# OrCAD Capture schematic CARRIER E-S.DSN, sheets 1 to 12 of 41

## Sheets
1 B0: size A4; title: Sistema Emulador Planta Generación Eólica; Carrier E/S para placa MicroZed; rev: 1.0; company: Oficina Técnica Universidad Carlos III de Madrid; note: OT-2017-4302
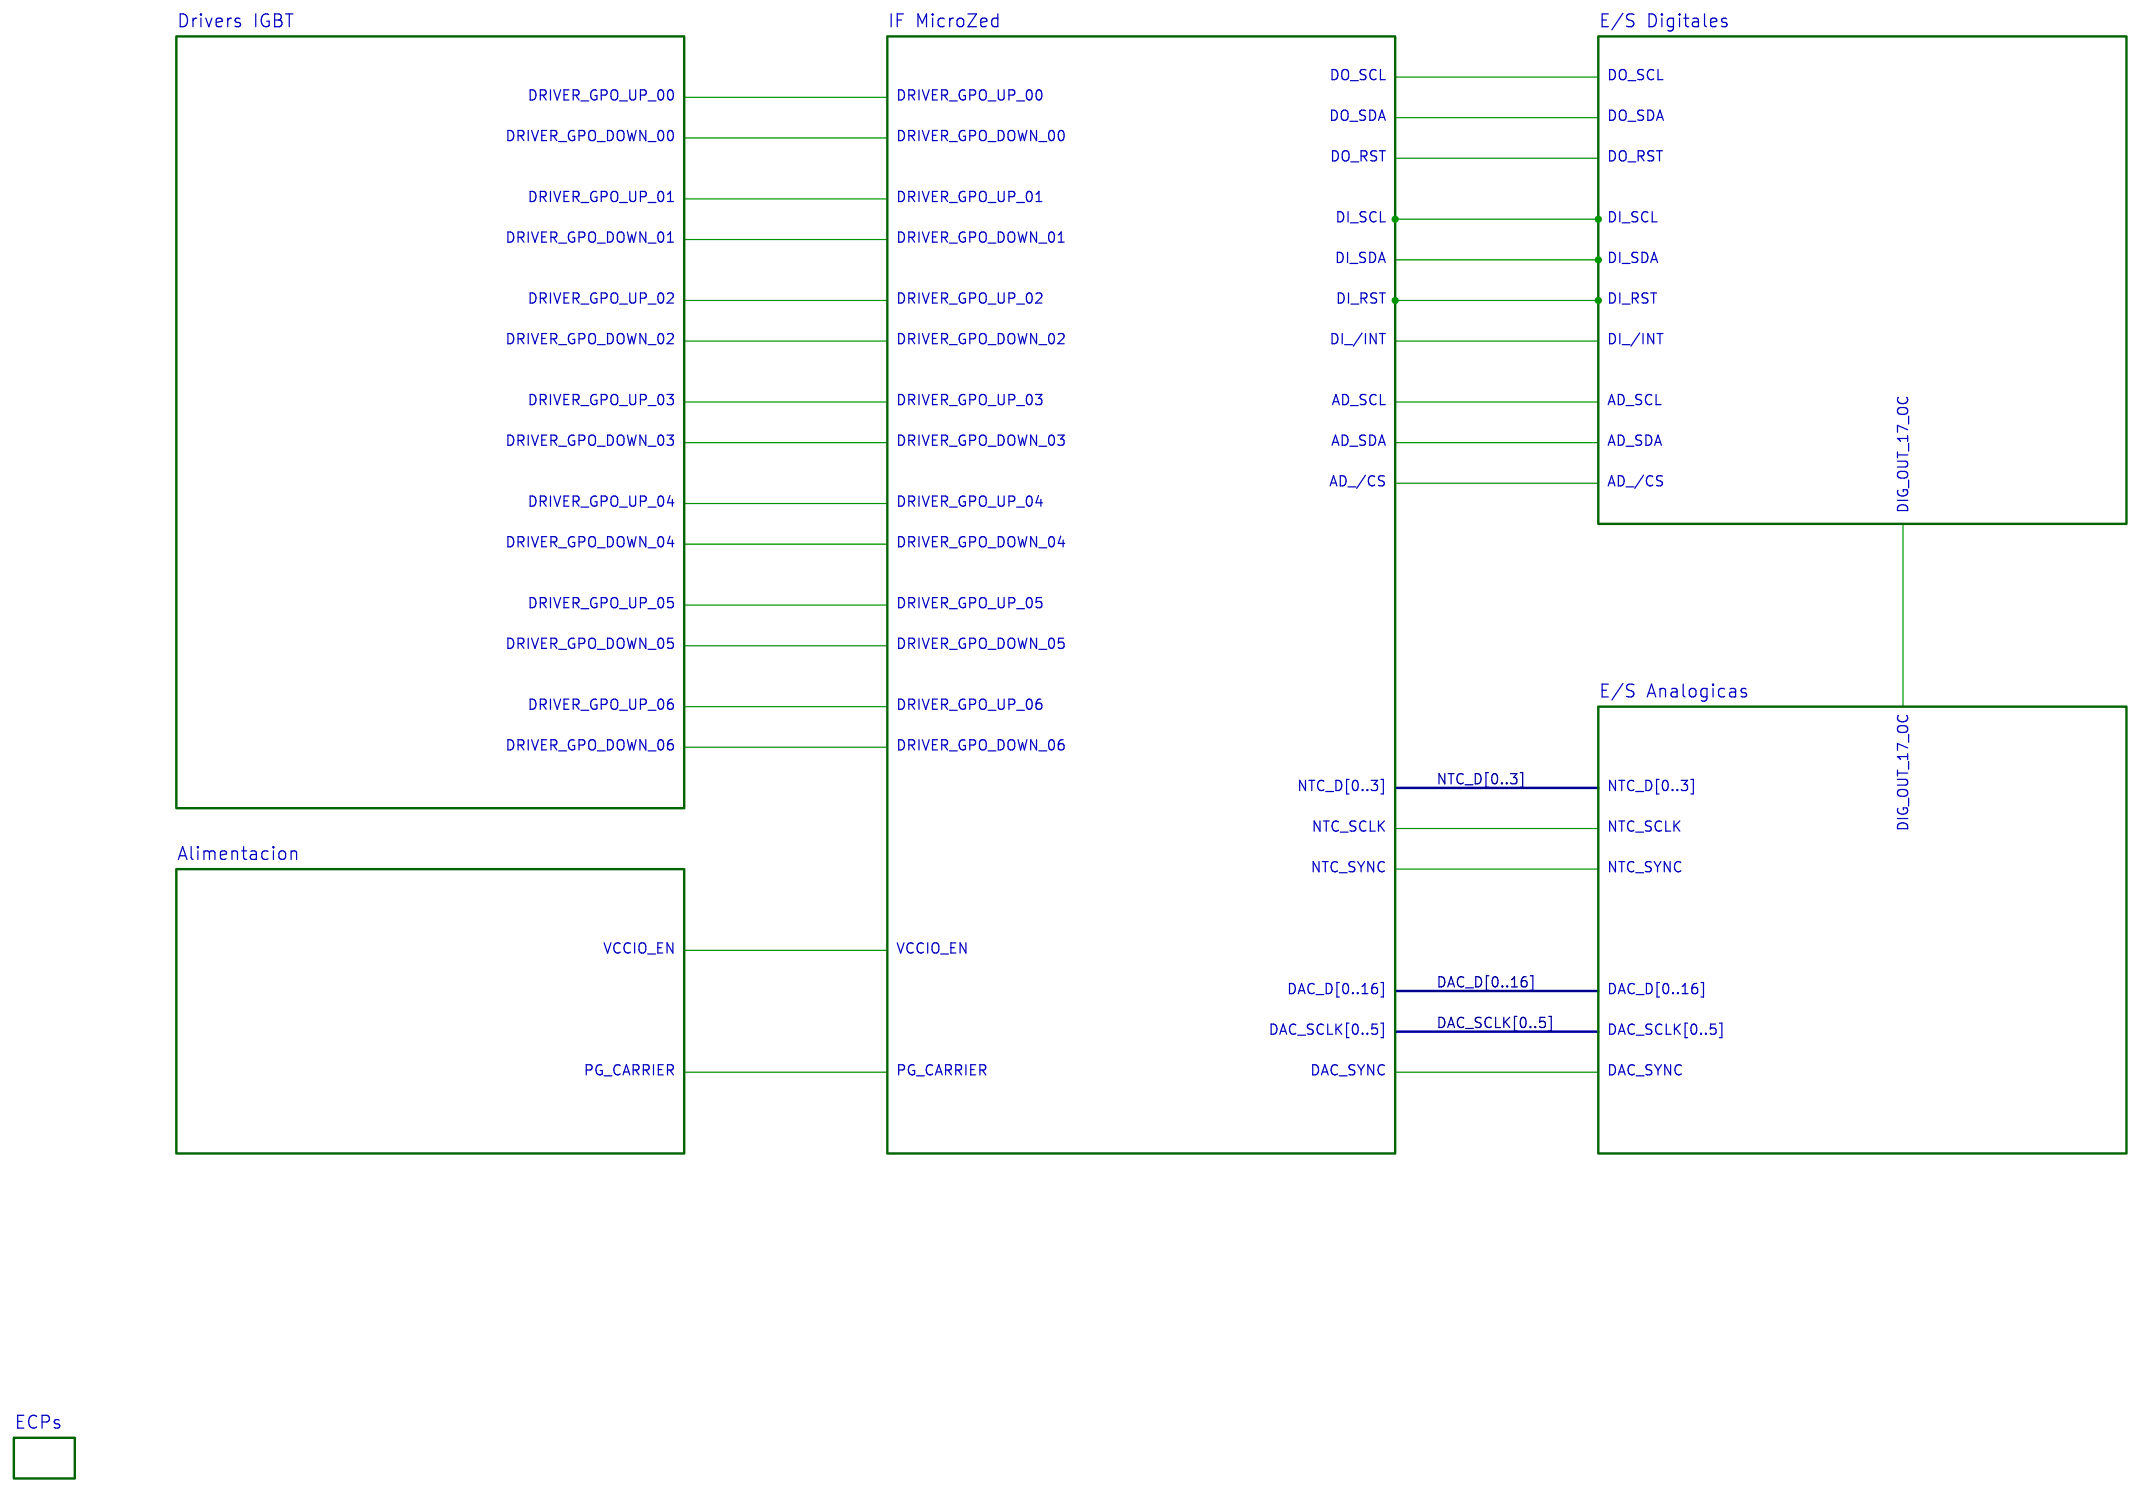
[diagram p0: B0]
2 B4B18
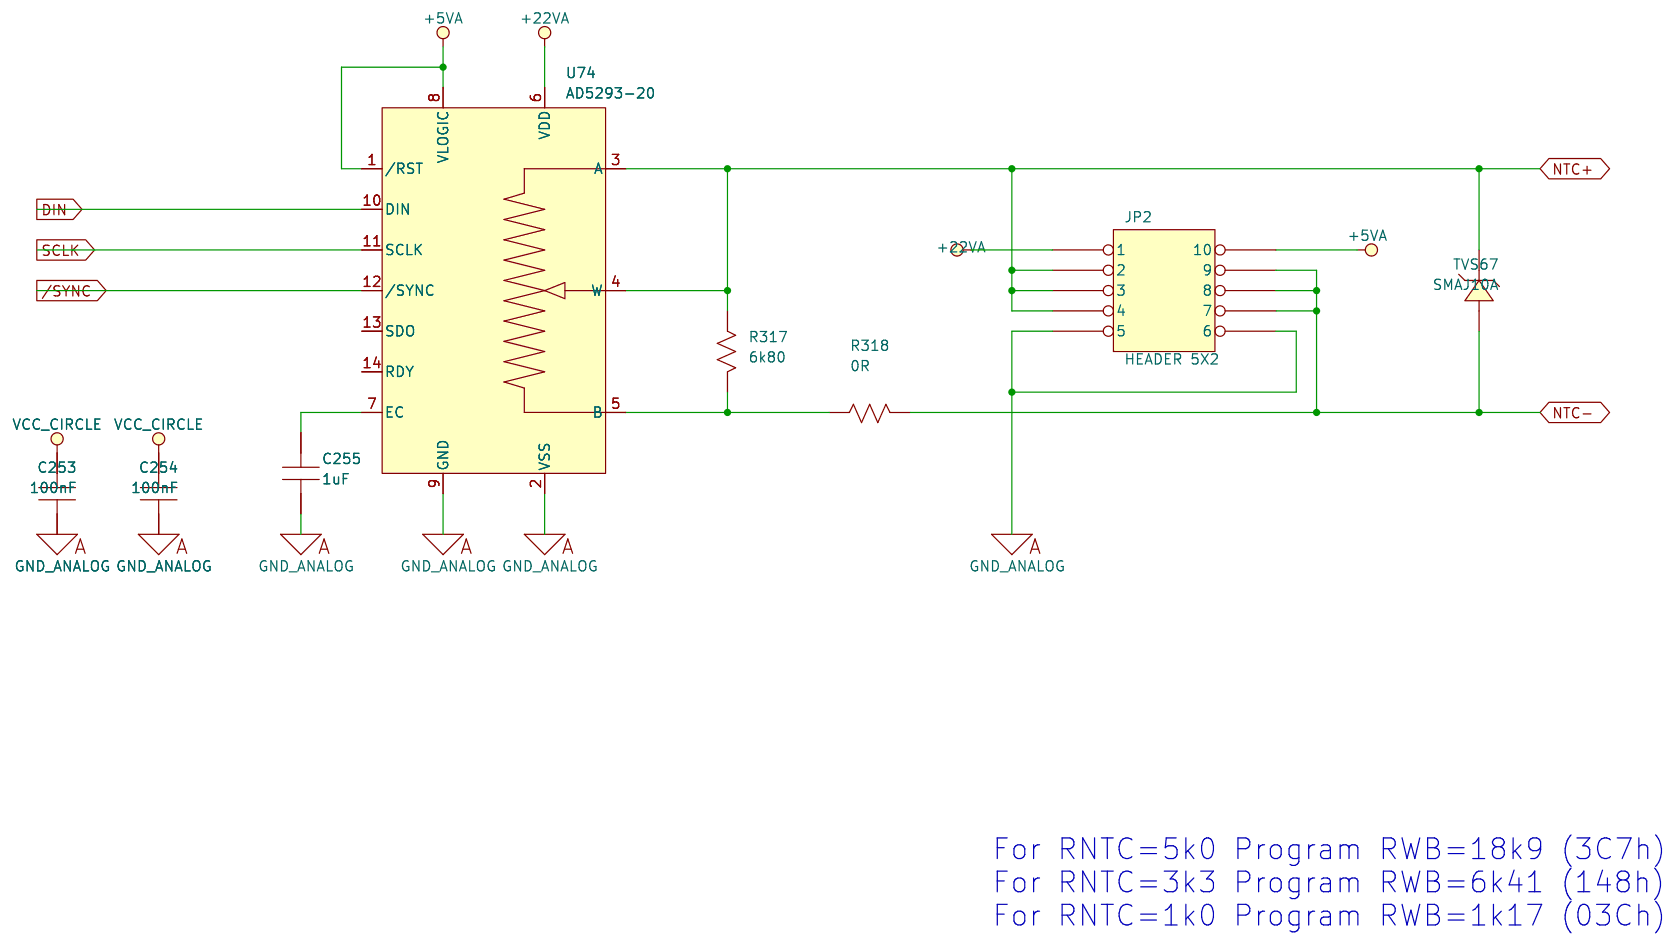
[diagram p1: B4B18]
3 B4B02
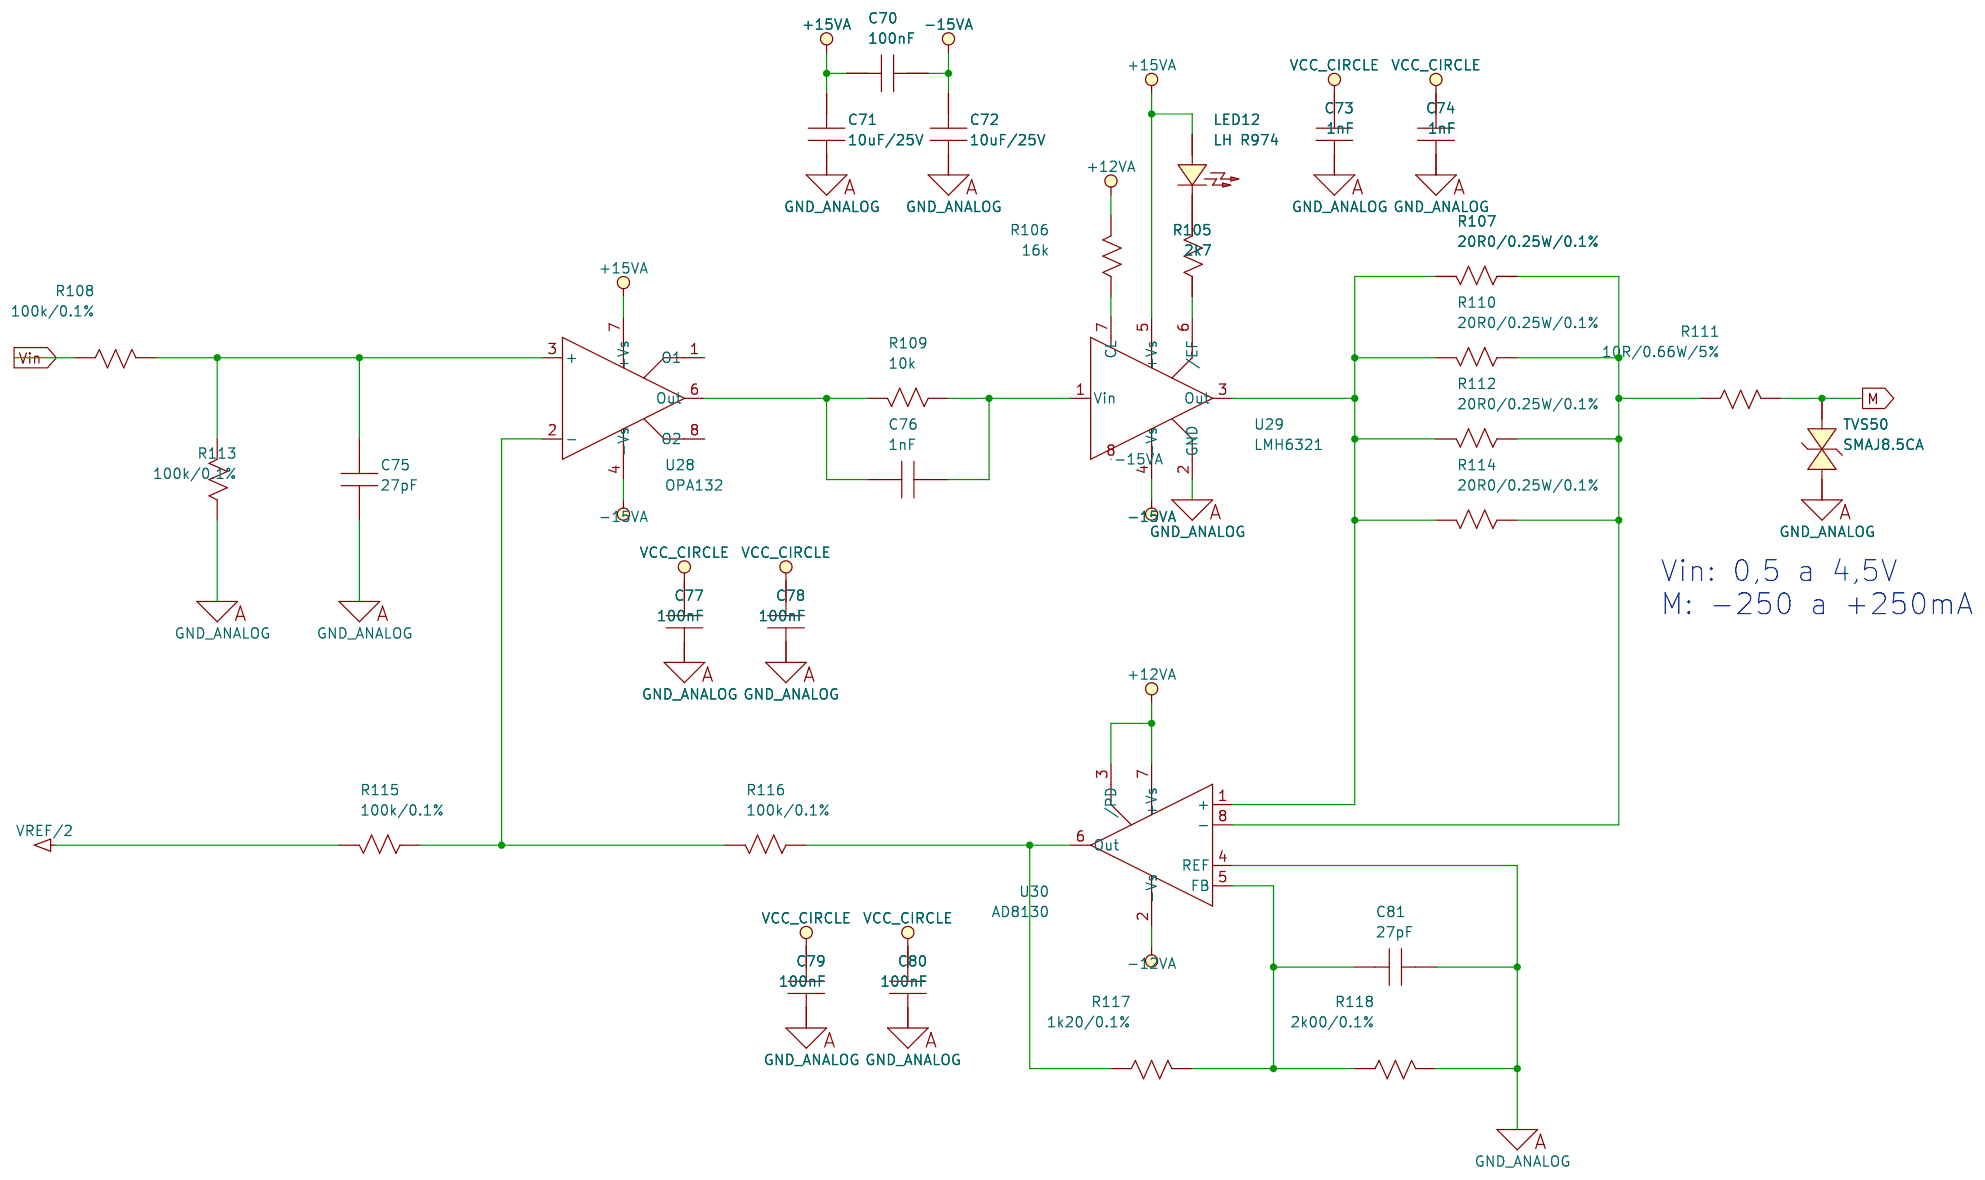
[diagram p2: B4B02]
4 B4B19
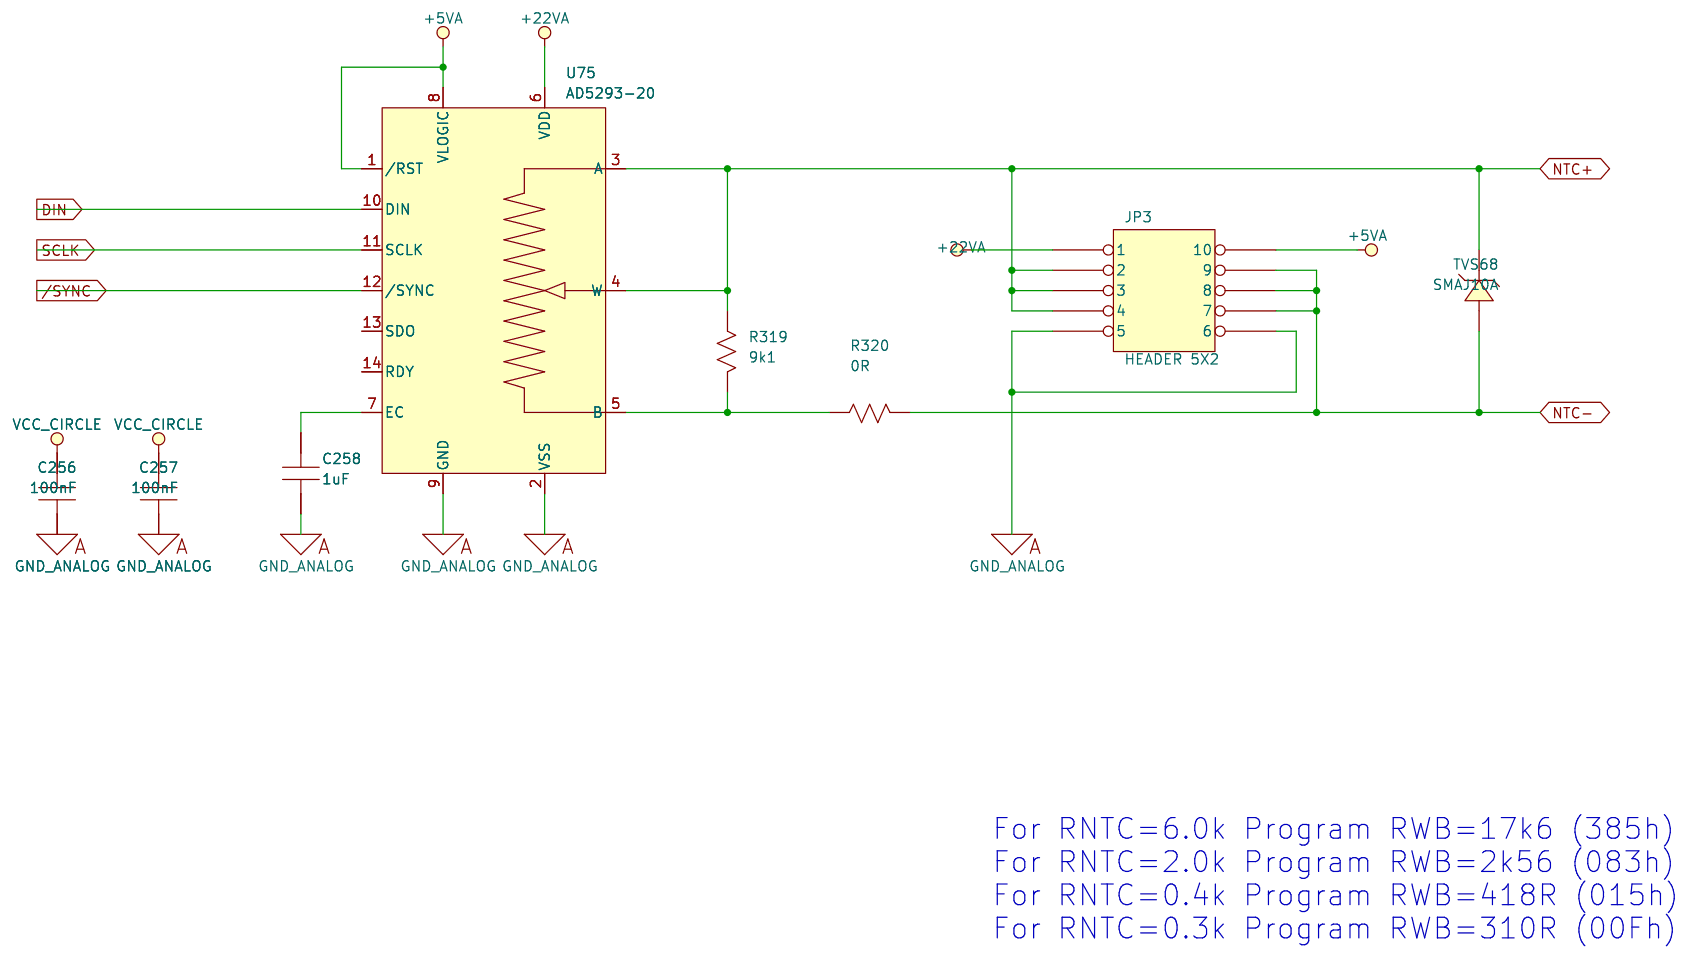
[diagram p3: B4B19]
5 B4B17
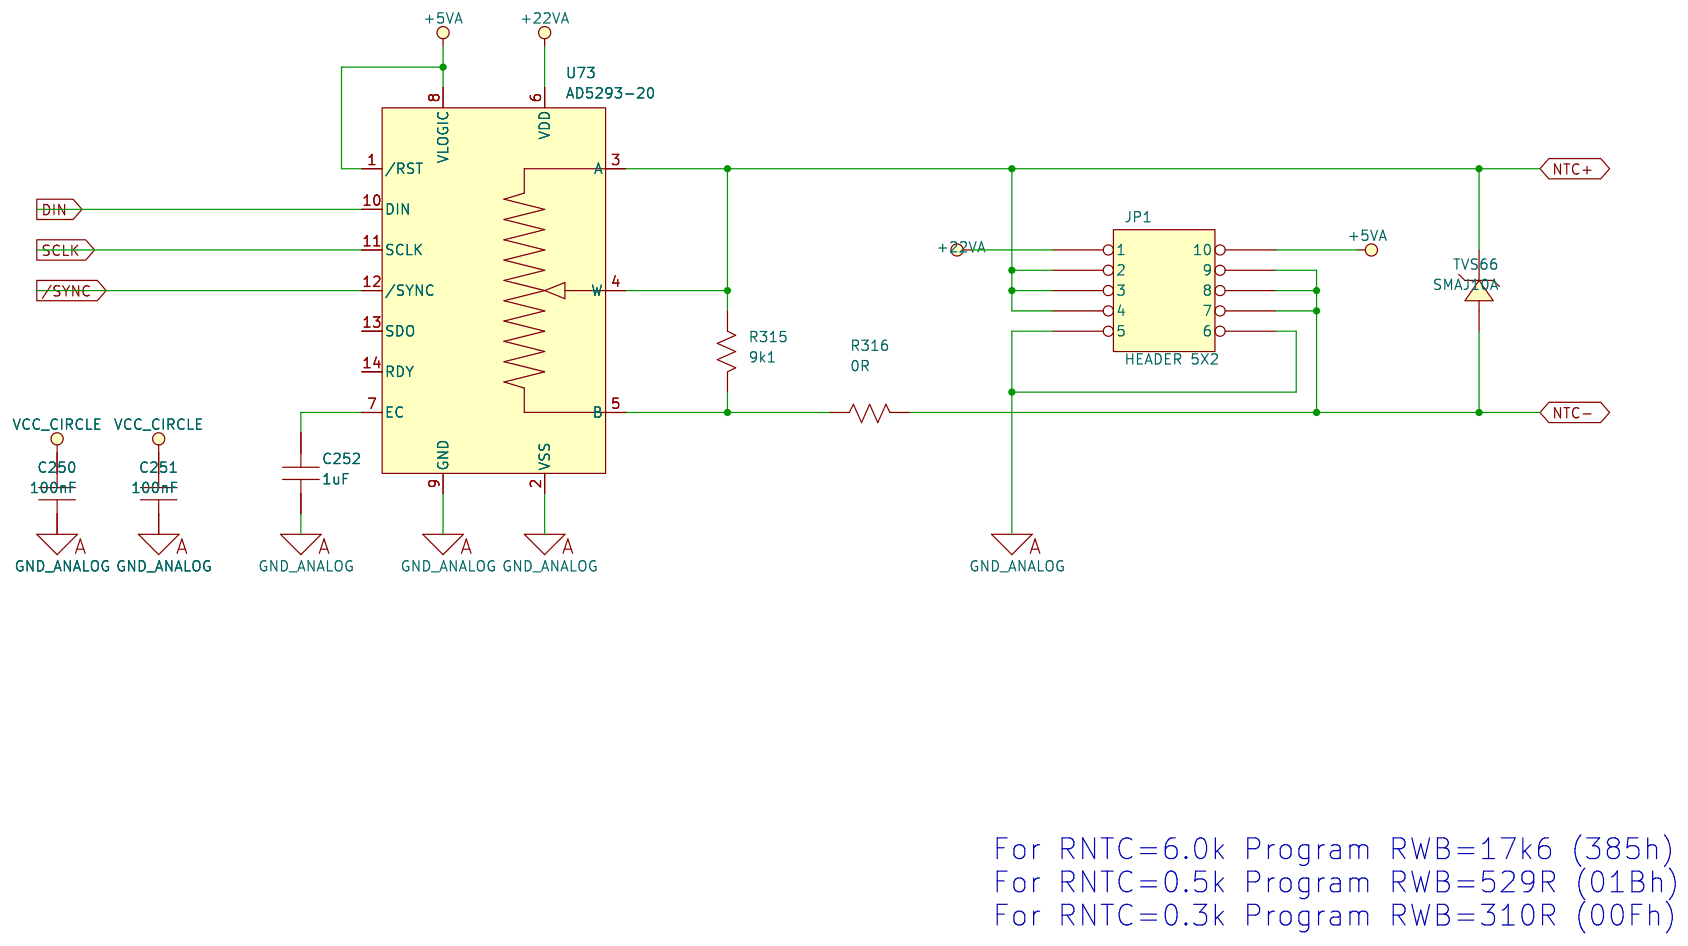
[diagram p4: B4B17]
6 B4B03
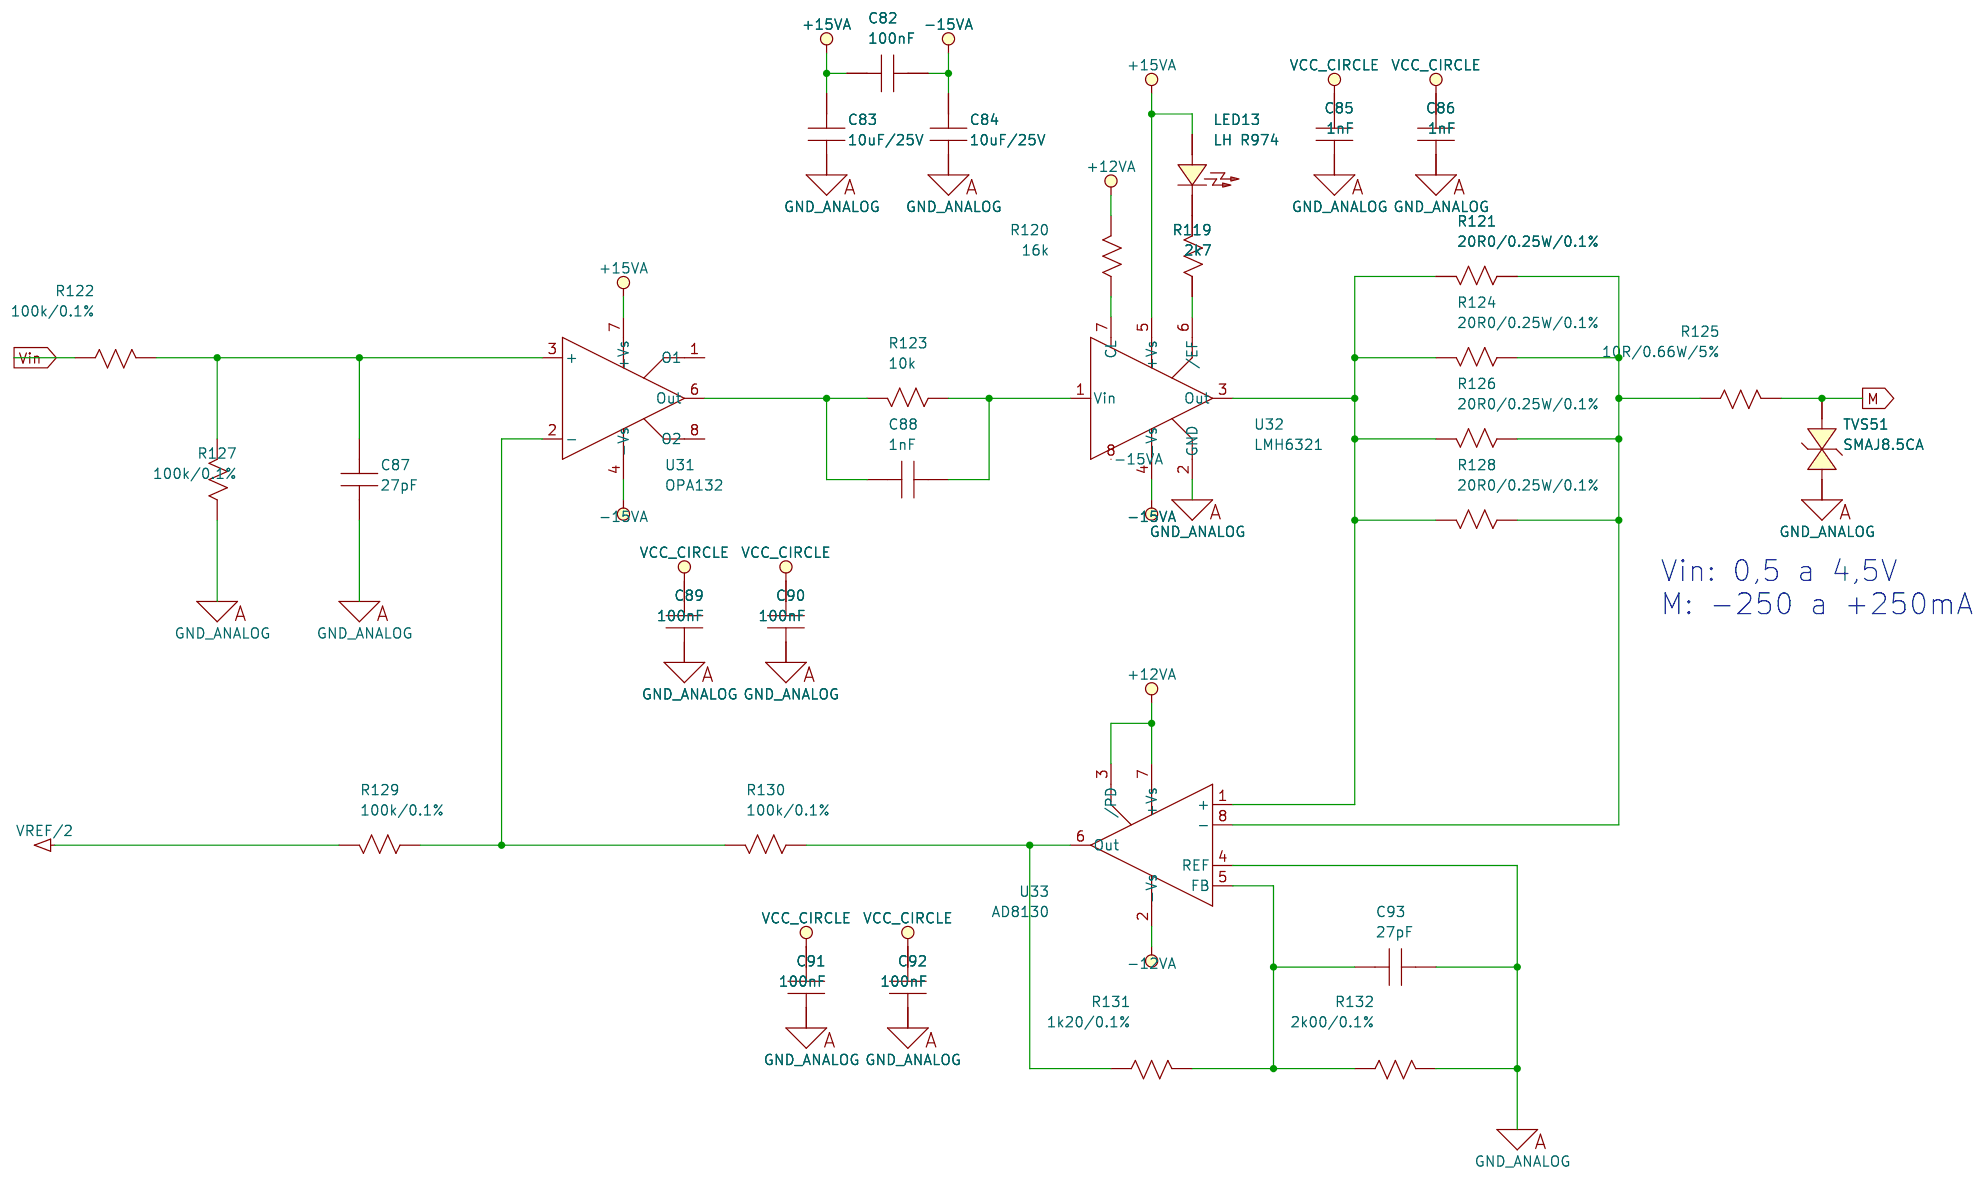
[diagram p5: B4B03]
7 B4B20
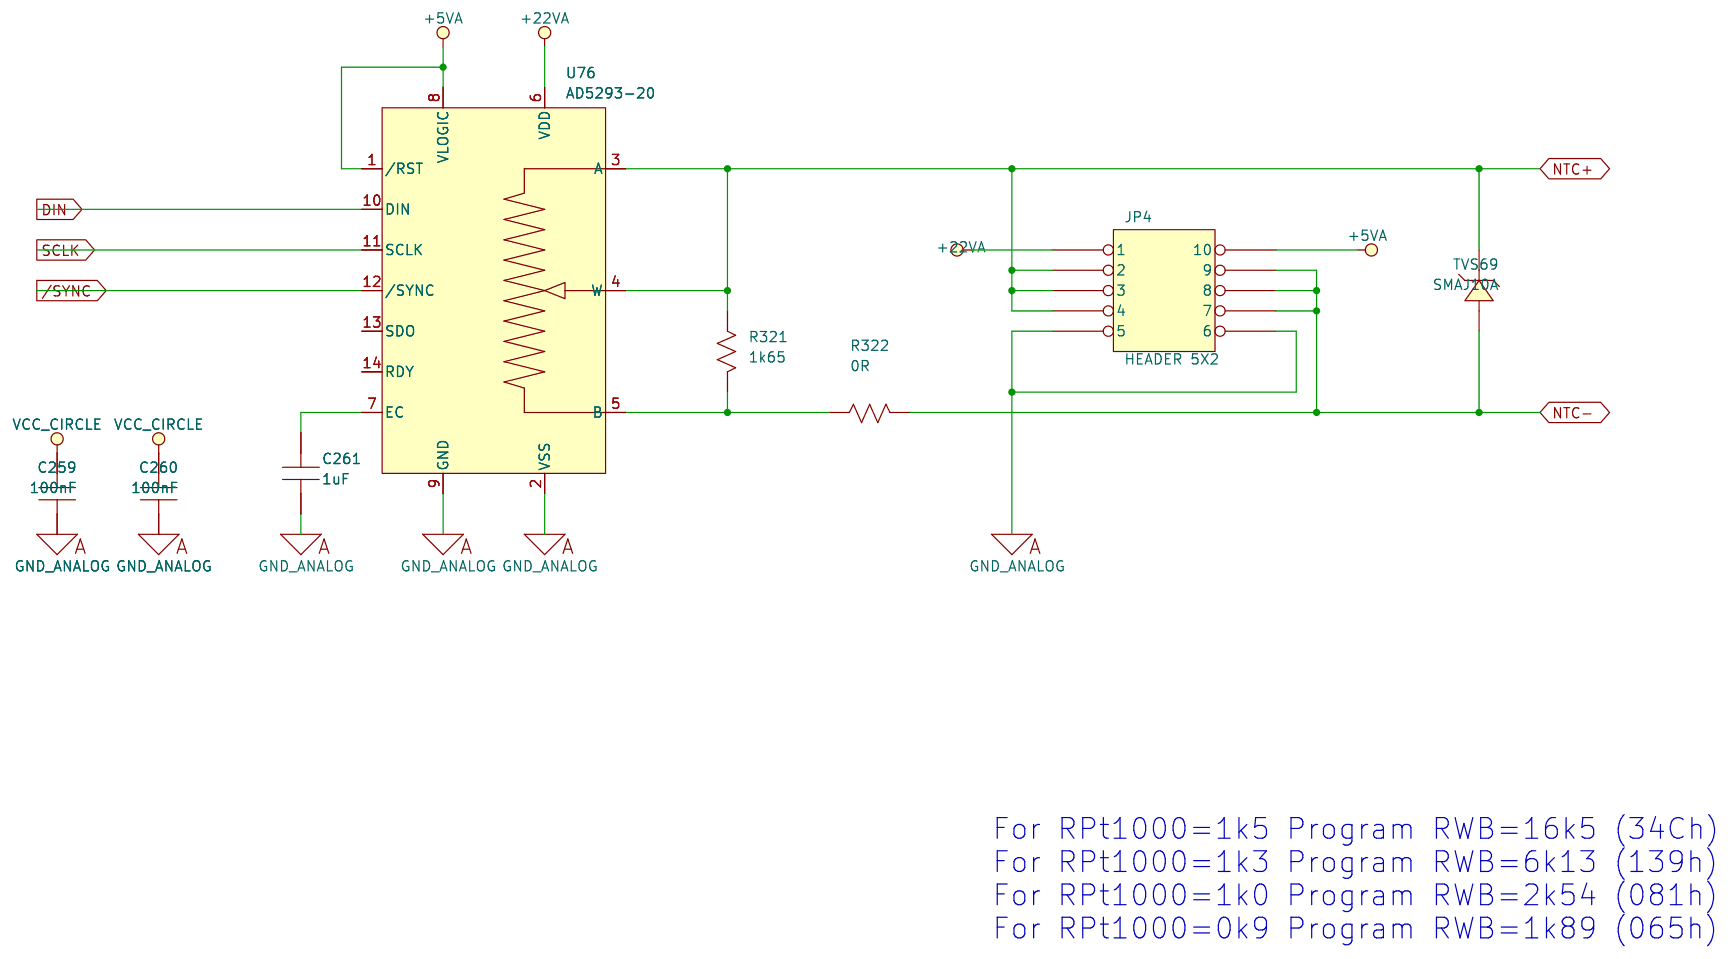
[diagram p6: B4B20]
8 B4B04
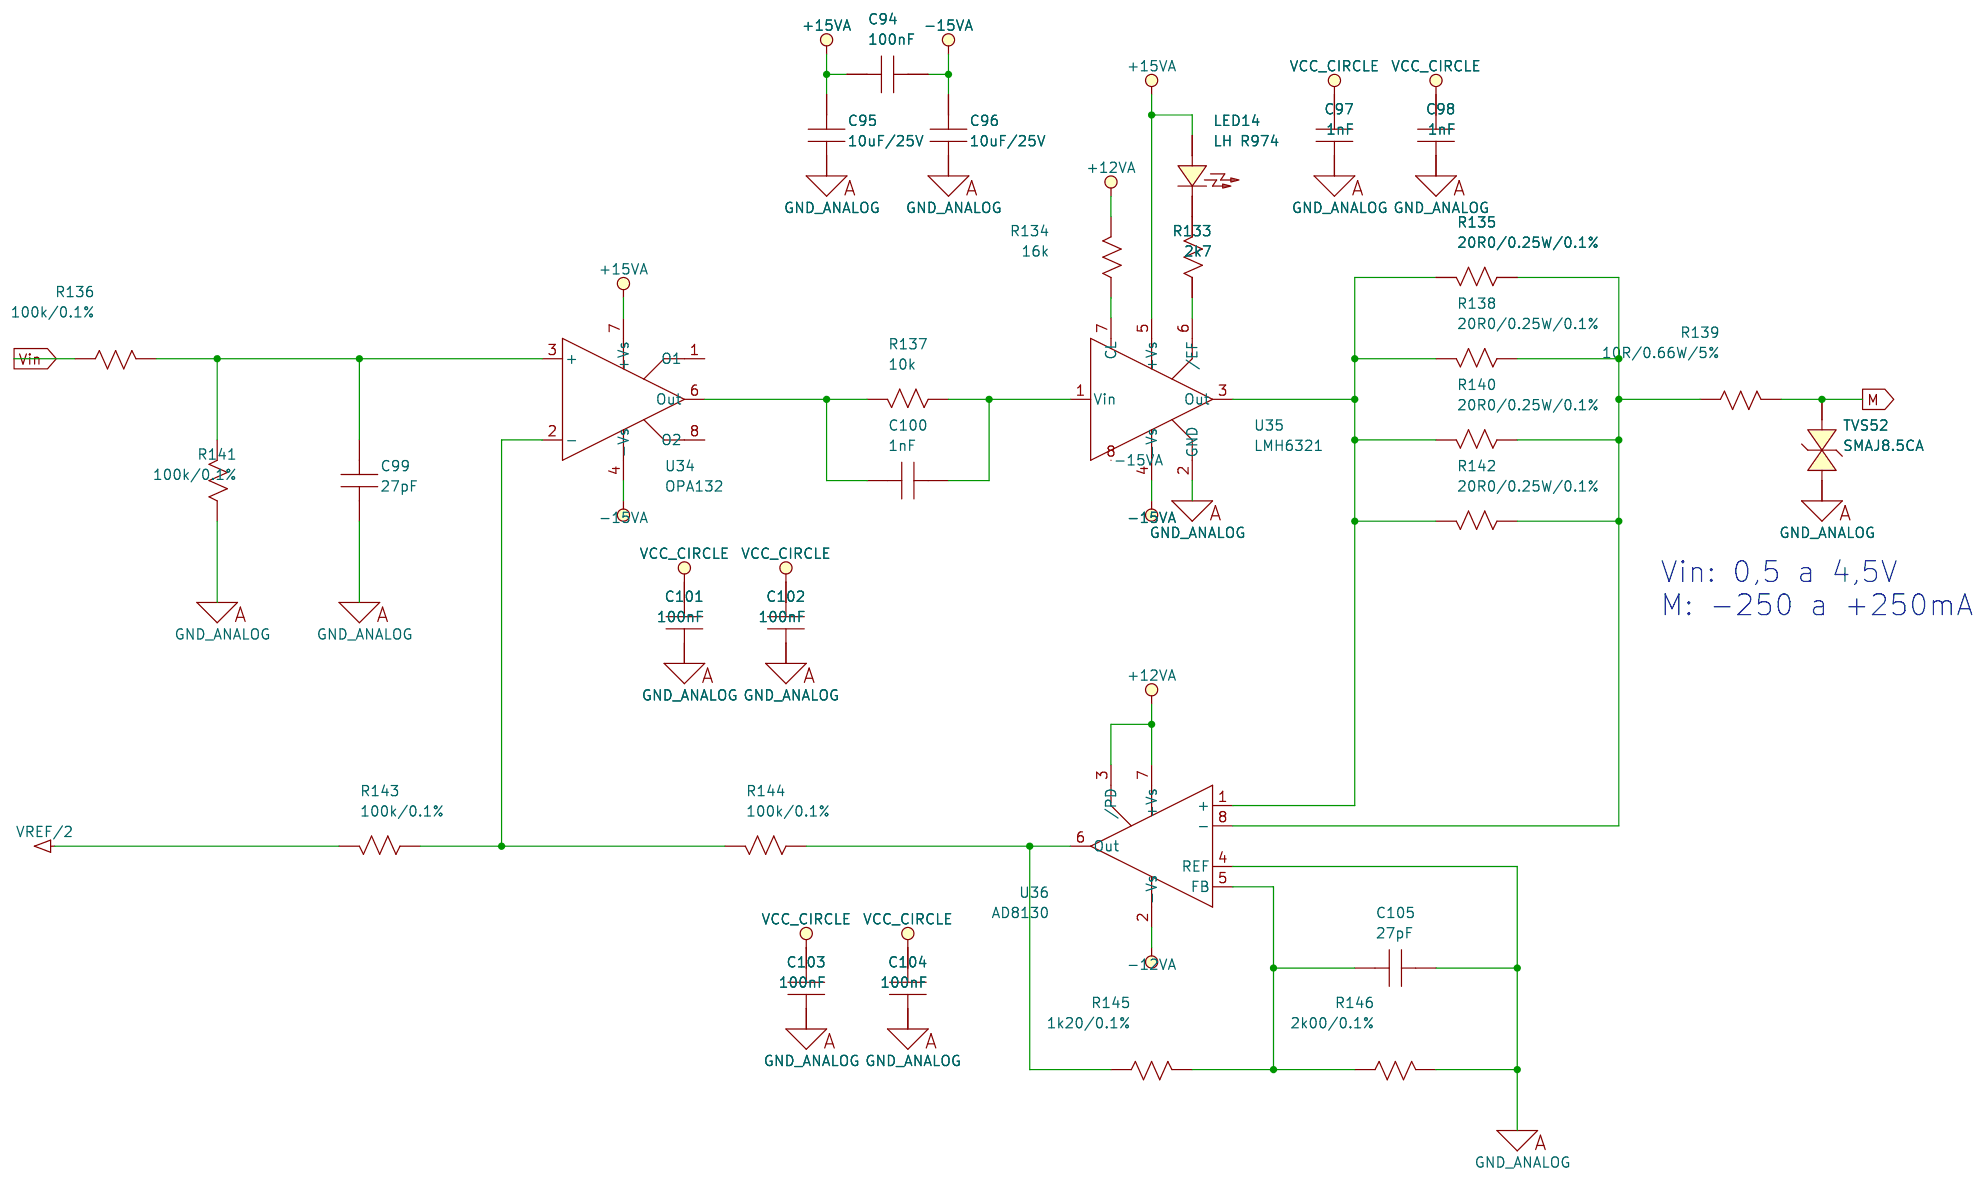
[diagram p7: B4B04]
9 B7B05
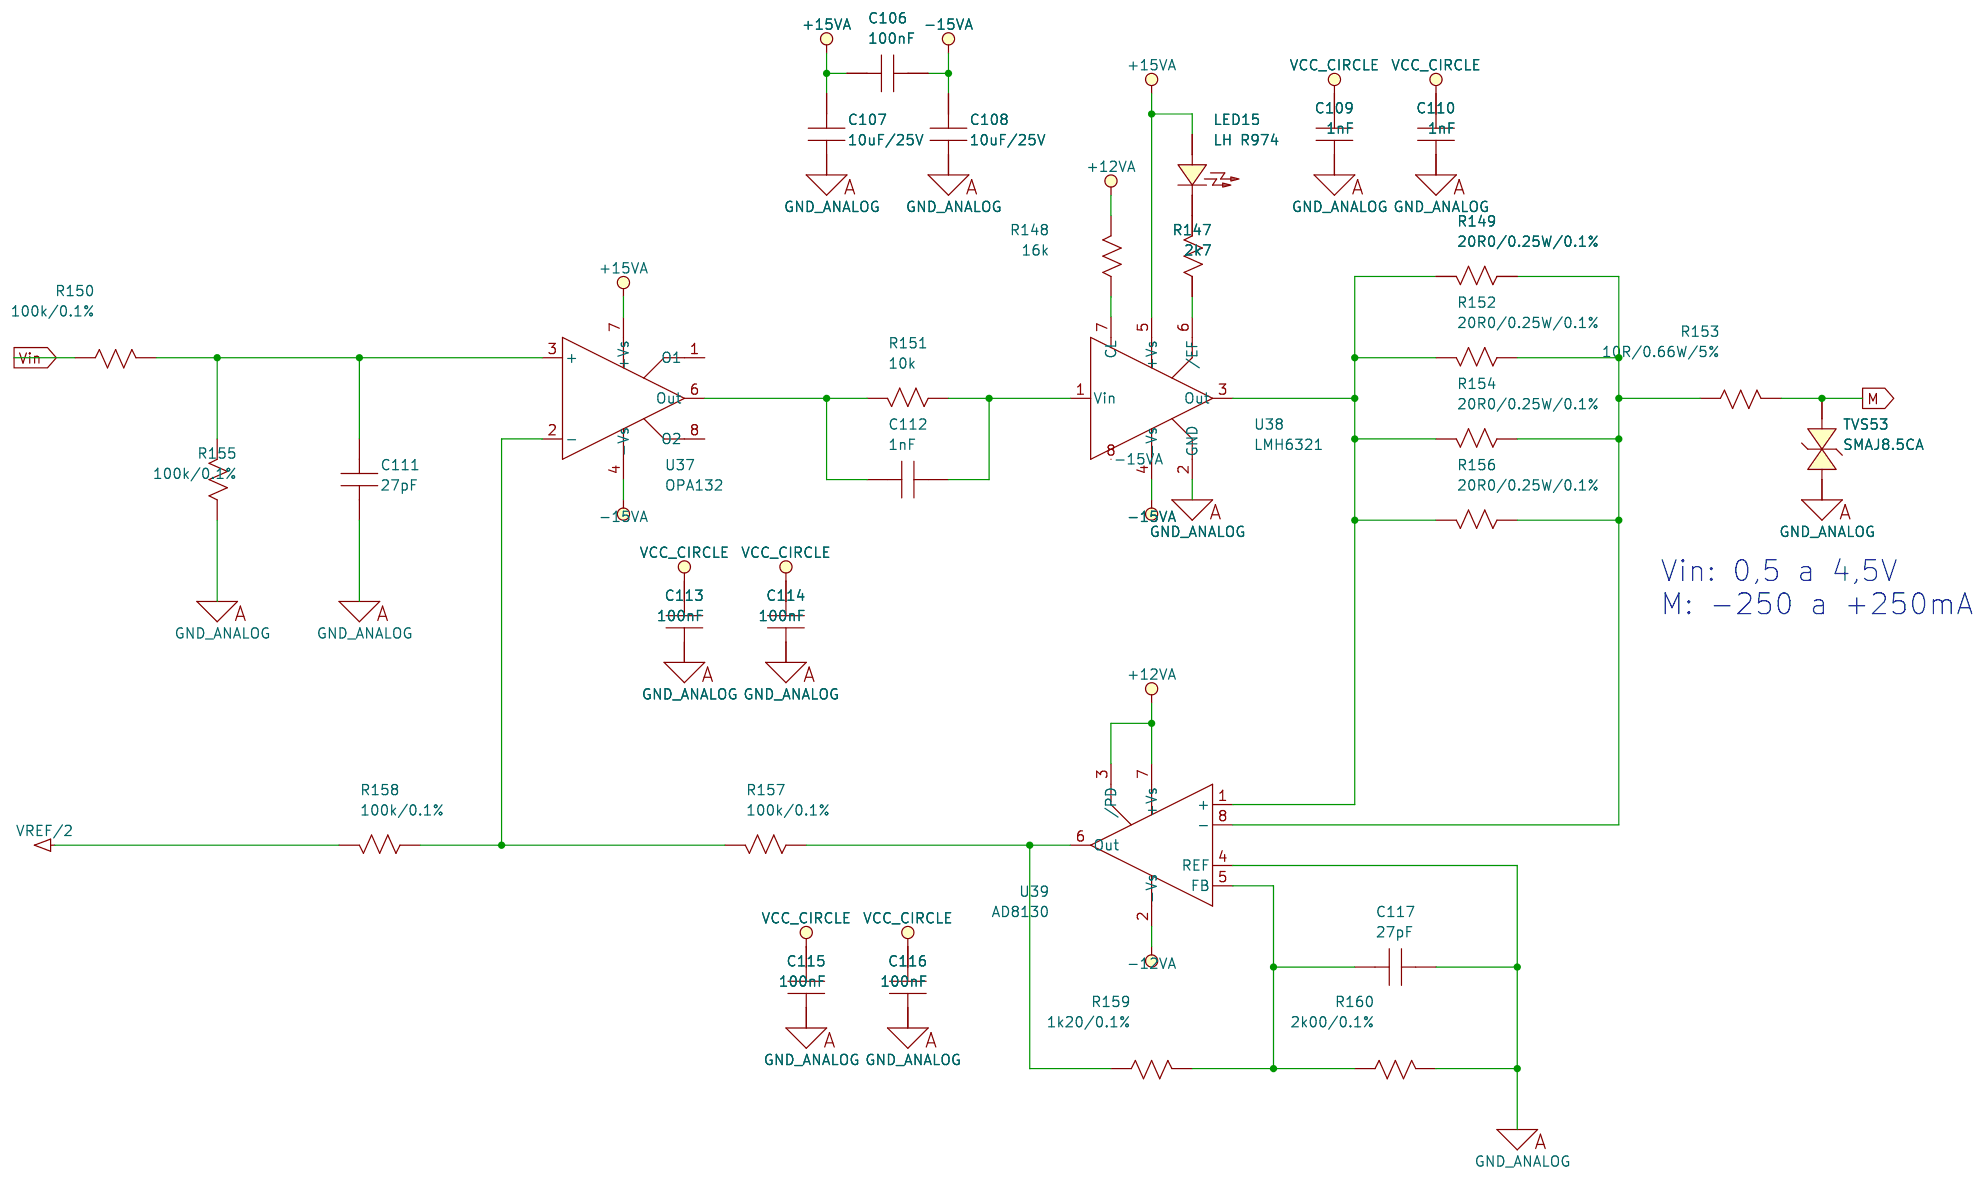
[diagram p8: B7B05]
10 B4B06
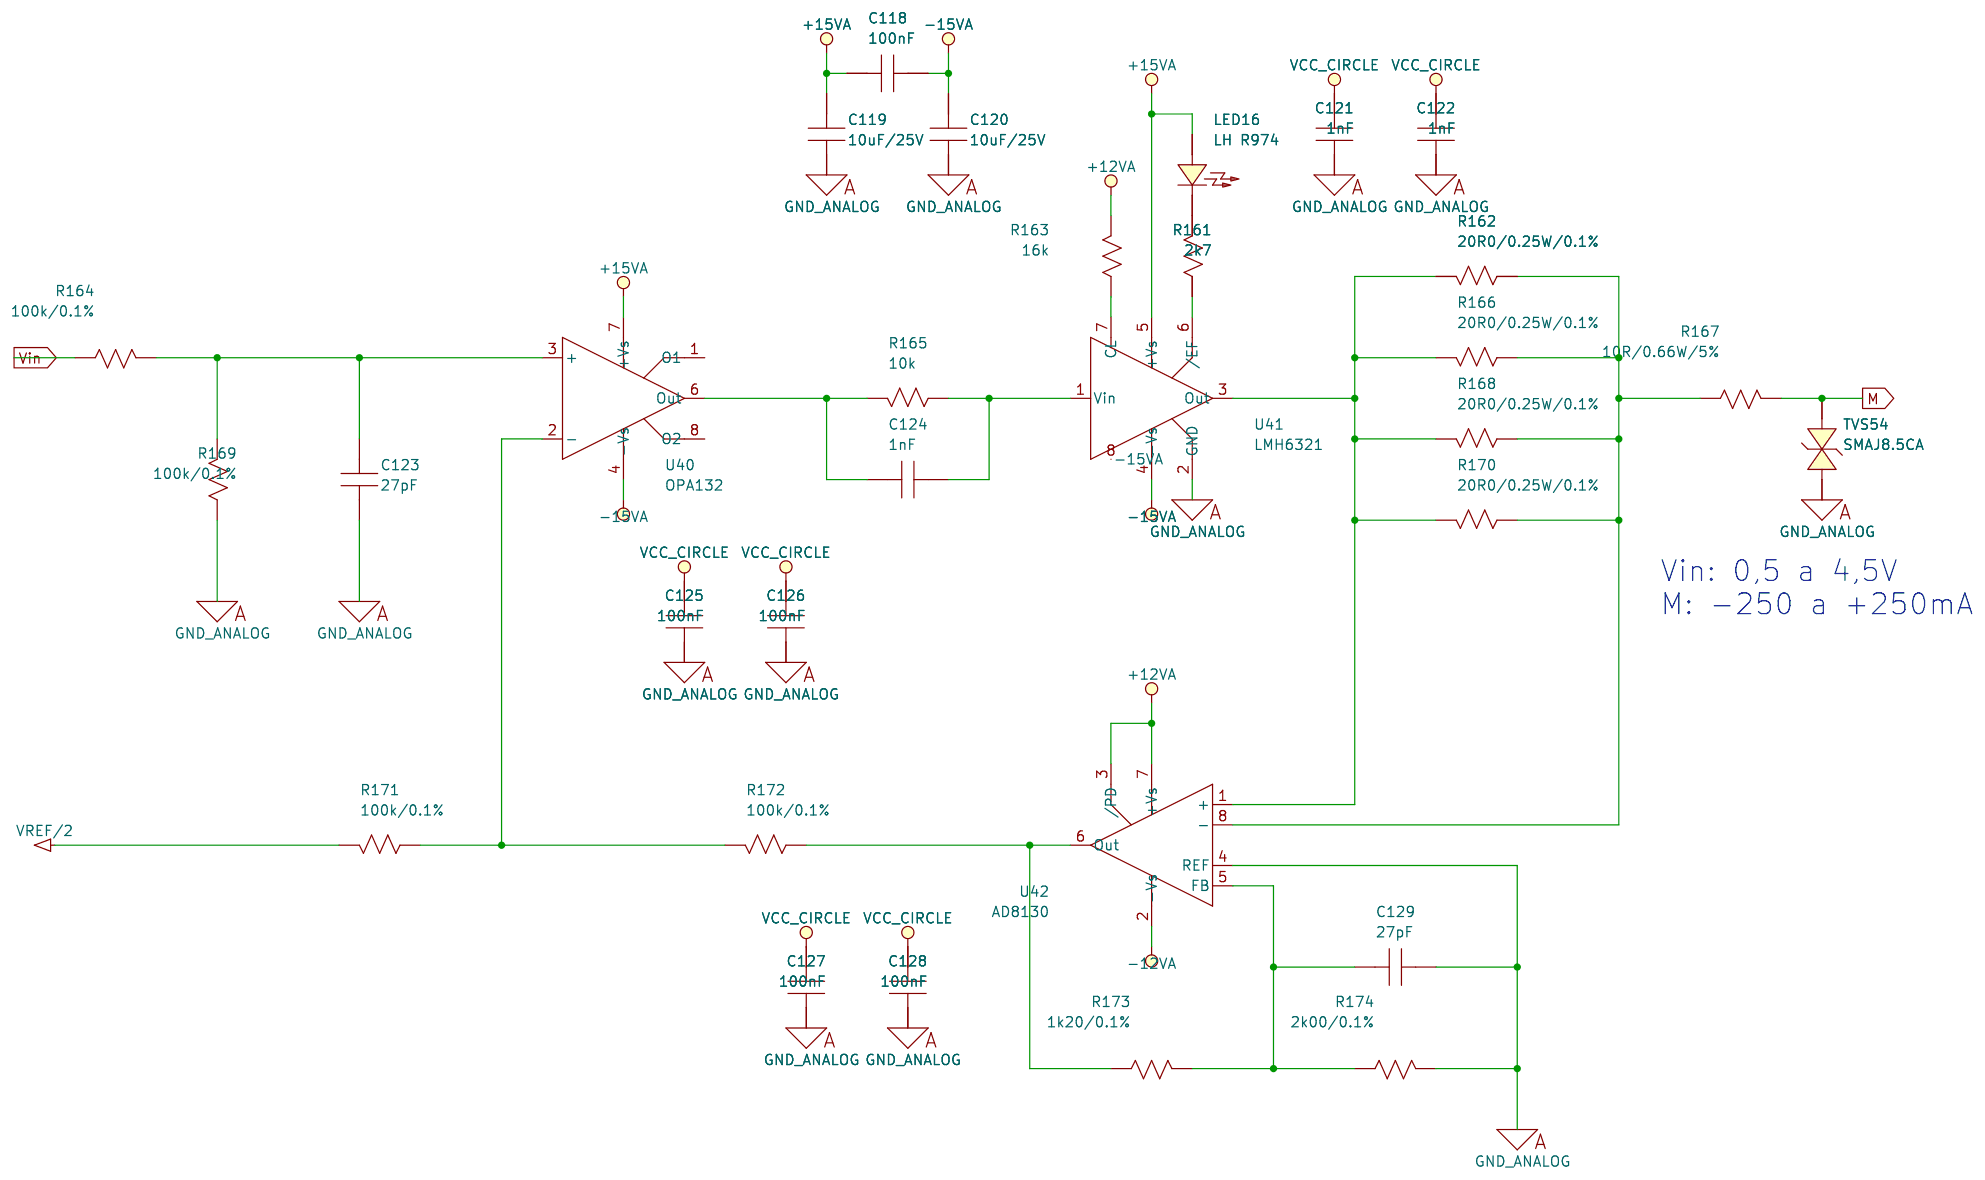
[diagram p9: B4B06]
11 B4B07
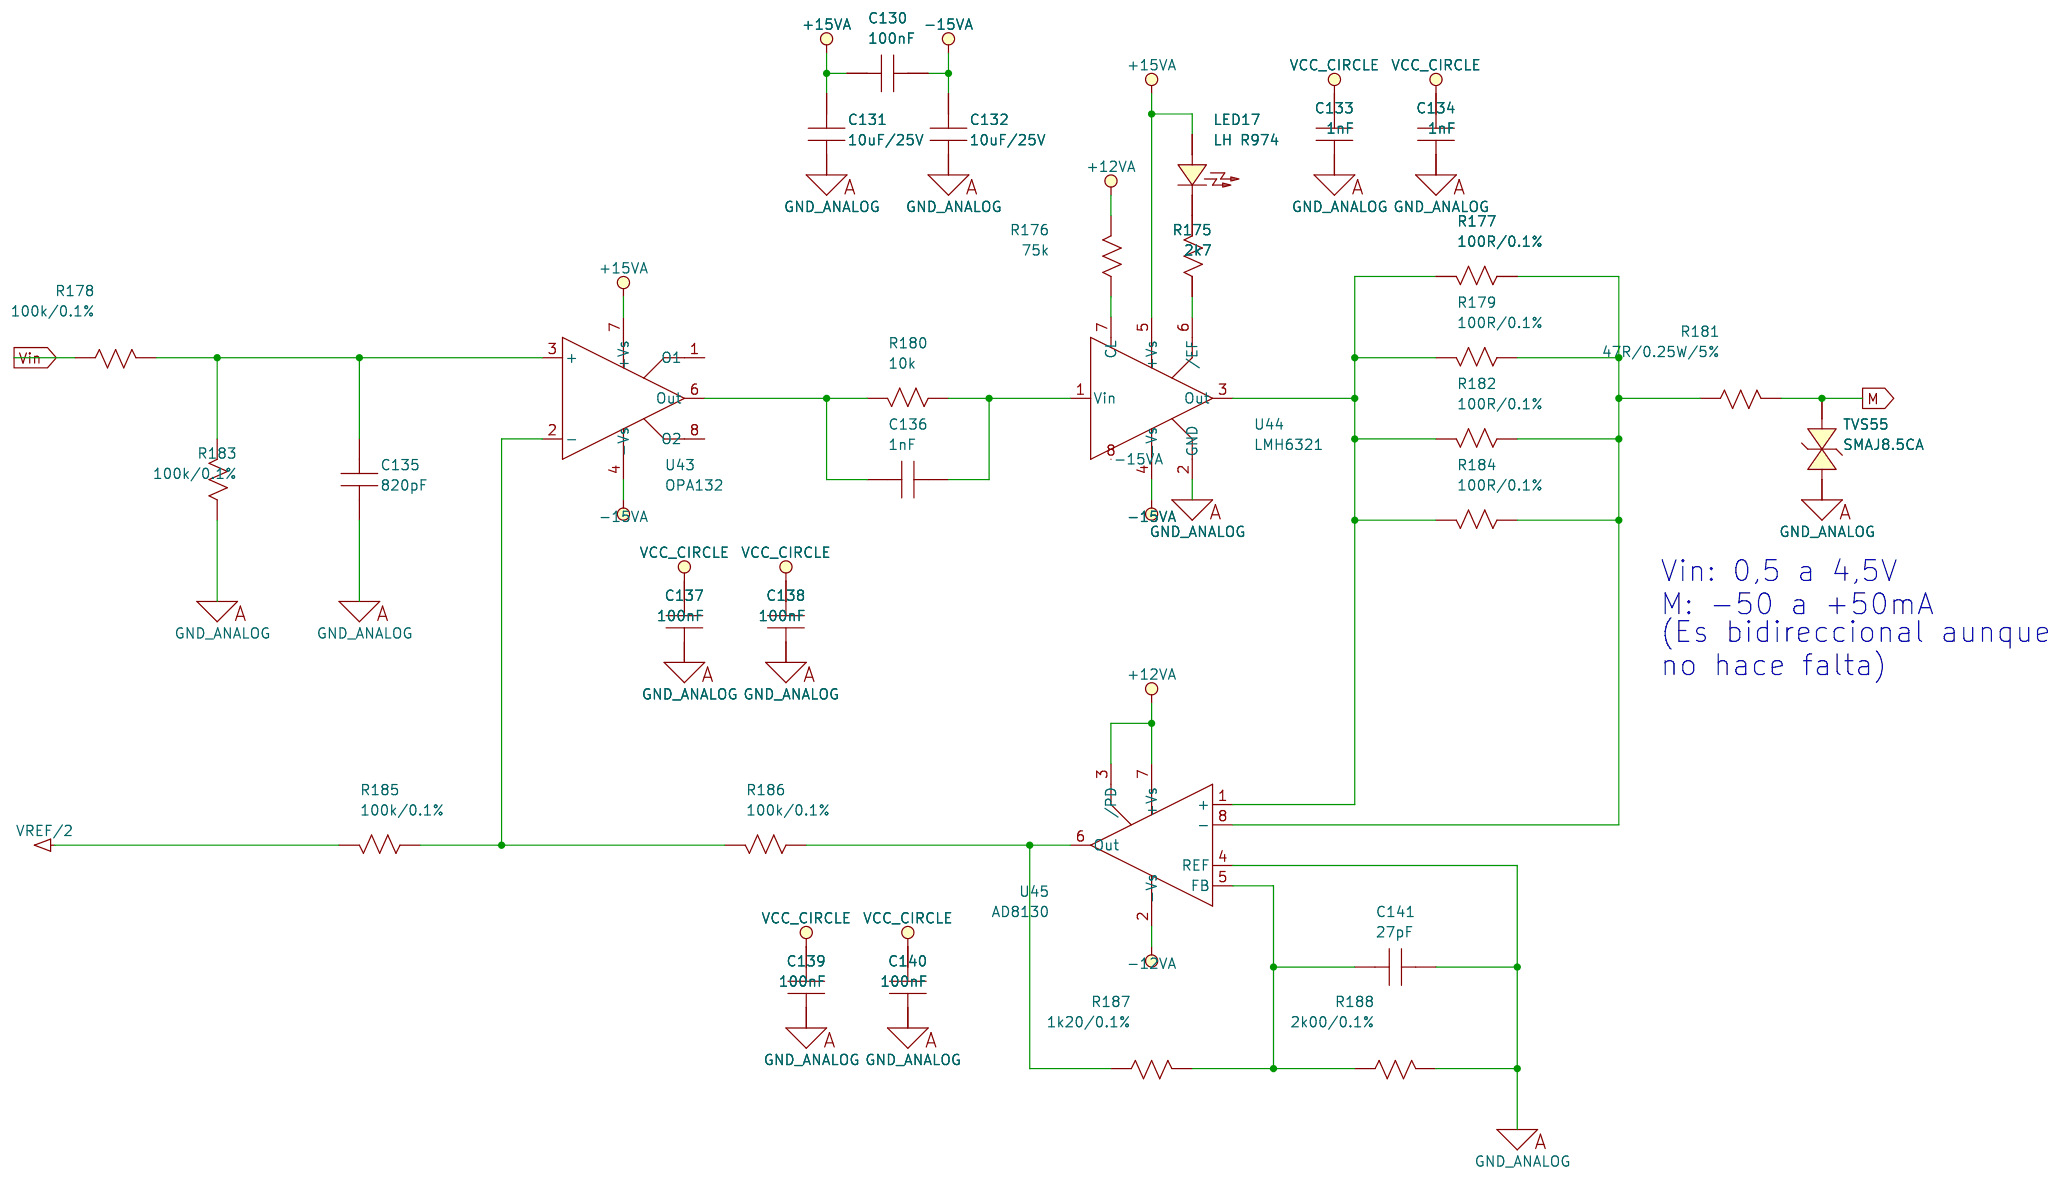
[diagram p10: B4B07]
12 B4B10
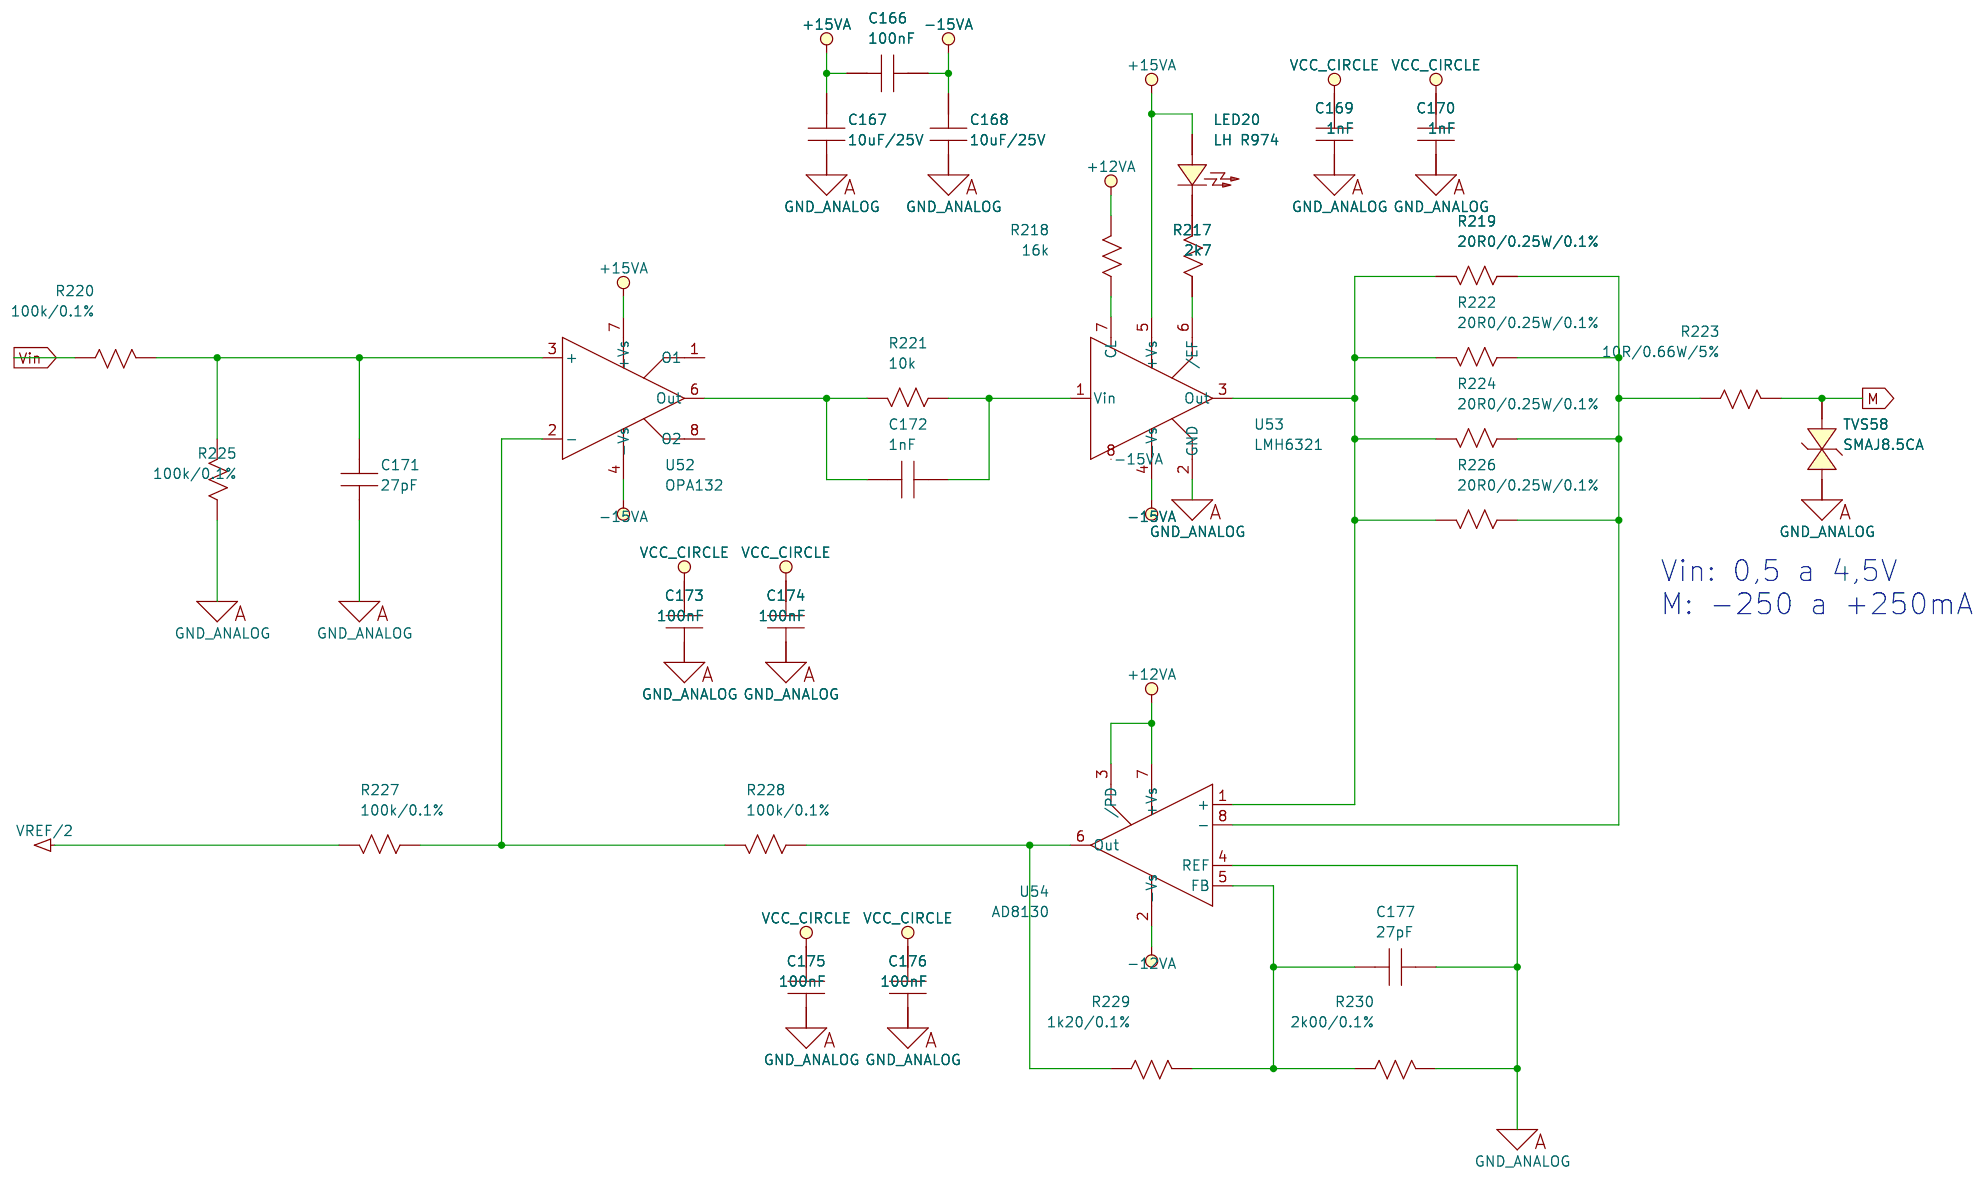
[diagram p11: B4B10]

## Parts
sheet B4B02
C70  100nF  [C/SM/0805/IPC-7351 (2005)/NORMAL]
C71  10uF/25V  [C/SM/1210/IPC-7351 (2005)/NORMAL]
C72  10uF/25V  [C/SM/1210/IPC-7351 (2005)/NORMAL]
C73  1nF  [C/SM/0805/IPC-7351 (2005)/NORMAL]
C74  1nF  [C/SM/0805/IPC-7351 (2005)/NORMAL]
C75  27pF  [C/SM/0805/IPC-7351 (2005)/NORMAL]
C76  1nF  [C/SM/0805/IPC-7351 (2005)/NORMAL]
C77  100nF  [C/SM/0805/IPC-7351 (2005)/NORMAL]
C78  100nF  [C/SM/0805/IPC-7351 (2005)/NORMAL]
C79  100nF  [C/SM/0805/IPC-7351 (2005)/NORMAL]
C80  100nF  [C/SM/0805/IPC-7351 (2005)/NORMAL]
C81  27pF  [C/SM/0805/IPC-7351 (2005)/NORMAL]
LED12  LH R974  [LED/SM/0805/IPC-7351 (2005)/NORMAL]
R105  2k7  [R/SM/0805/IPC-7351 (2005)/NORMAL]
R106  16k  [R/SM/0805/IPC-7351 (2005)/NORMAL]
R107  20R0/0.25W/0.1%  [R/SM/1206/IPC-7351 (2005)/NORMAL]
R108  100k/0.1%  [R/SM/0805/IPC-7351 (2005)/NORMAL]
R109  10k  [R/SM/0805/IPC-7351 (2005)/NORMAL]
R110  20R0/0.25W/0.1%  [R/SM/1206/IPC-7351 (2005)/NORMAL]
R111  10R/0.66W/5%  [R/SM/1206/IPC-7351 (2005)/NORMAL]
R112  20R0/0.25W/0.1%  [R/SM/1206/IPC-7351 (2005)/NORMAL]
R113  100k/0.1%  [R/SM/0805/IPC-7351 (2005)/NORMAL]
R114  20R0/0.25W/0.1%  [R/SM/1206/IPC-7351 (2005)/NORMAL]
R115  100k/0.1%  [R/SM/0805/IPC-7351 (2005)/NORMAL]
R116  100k/0.1%  [R/SM/0805/IPC-7351 (2005)/NORMAL]
R117  1k20/0.1%  [R/SM/0805/IPC-7351 (2005)/NORMAL]
R118  2k00/0.1%  [R/SM/0805/IPC-7351 (2005)/NORMAL]
TVS50  SMAJ8.5CA  [SM/DO214AC/IPC-7351 (2005)/NORMAL]
U28  OPA132  [SM/SOIC.050/08/WB.150/L.200/IPC-7351 (2005)/NORMAL]
U29  LMH6321  [SM/TO263/D2PAK/THV 42X.012/7/IPC-7351 (2005)/NORMAL]
U30  AD8130  [SM/SOIC.050/08/WB.150/L.200/IPC-7351 (2005)/NORMAL]
sheet B4B03
C82  100nF  [C/SM/0805/IPC-7351 (2005)/NORMAL]
C83  10uF/25V  [C/SM/1210/IPC-7351 (2005)/NORMAL]
C84  10uF/25V  [C/SM/1210/IPC-7351 (2005)/NORMAL]
C85  1nF  [C/SM/0805/IPC-7351 (2005)/NORMAL]
C86  1nF  [C/SM/0805/IPC-7351 (2005)/NORMAL]
C87  27pF  [C/SM/0805/IPC-7351 (2005)/NORMAL]
C88  1nF  [C/SM/0805/IPC-7351 (2005)/NORMAL]
C89  100nF  [C/SM/0805/IPC-7351 (2005)/NORMAL]
C90  100nF  [C/SM/0805/IPC-7351 (2005)/NORMAL]
C91  100nF  [C/SM/0805/IPC-7351 (2005)/NORMAL]
C92  100nF  [C/SM/0805/IPC-7351 (2005)/NORMAL]
C93  27pF  [C/SM/0805/IPC-7351 (2005)/NORMAL]
LED13  LH R974  [LED/SM/0805/IPC-7351 (2005)/NORMAL]
R119  2k7  [R/SM/0805/IPC-7351 (2005)/NORMAL]
R120  16k  [R/SM/0805/IPC-7351 (2005)/NORMAL]
R121  20R0/0.25W/0.1%  [R/SM/1206/IPC-7351 (2005)/NORMAL]
R122  100k/0.1%  [R/SM/0805/IPC-7351 (2005)/NORMAL]
R123  10k  [R/SM/0805/IPC-7351 (2005)/NORMAL]
R124  20R0/0.25W/0.1%  [R/SM/1206/IPC-7351 (2005)/NORMAL]
R125  10R/0.66W/5%  [R/SM/1206/IPC-7351 (2005)/NORMAL]
R126  20R0/0.25W/0.1%  [R/SM/1206/IPC-7351 (2005)/NORMAL]
R127  100k/0.1%  [R/SM/0805/IPC-7351 (2005)/NORMAL]
R128  20R0/0.25W/0.1%  [R/SM/1206/IPC-7351 (2005)/NORMAL]
R129  100k/0.1%  [R/SM/0805/IPC-7351 (2005)/NORMAL]
R130  100k/0.1%  [R/SM/0805/IPC-7351 (2005)/NORMAL]
R131  1k20/0.1%  [R/SM/0805/IPC-7351 (2005)/NORMAL]
R132  2k00/0.1%  [R/SM/0805/IPC-7351 (2005)/NORMAL]
TVS51  SMAJ8.5CA  [SM/DO214AC/IPC-7351 (2005)/NORMAL]
U31  OPA132  [SM/SOIC.050/08/WB.150/L.200/IPC-7351 (2005)/NORMAL]
U32  LMH6321  [SM/TO263/D2PAK/THV 42X.012/7/IPC-7351 (2005)/NORMAL]
U33  AD8130  [SM/SOIC.050/08/WB.150/L.200/IPC-7351 (2005)/NORMAL]
sheet B4B04
C94  100nF  [C/SM/0805/IPC-7351 (2005)/NORMAL]
C95  10uF/25V  [C/SM/1210/IPC-7351 (2005)/NORMAL]
C96  10uF/25V  [C/SM/1210/IPC-7351 (2005)/NORMAL]
C97  1nF  [C/SM/0805/IPC-7351 (2005)/NORMAL]
C98  1nF  [C/SM/0805/IPC-7351 (2005)/NORMAL]
C99  27pF  [C/SM/0805/IPC-7351 (2005)/NORMAL]
C100  1nF  [C/SM/0805/IPC-7351 (2005)/NORMAL]
C101  100nF  [C/SM/0805/IPC-7351 (2005)/NORMAL]
C102  100nF  [C/SM/0805/IPC-7351 (2005)/NORMAL]
C103  100nF  [C/SM/0805/IPC-7351 (2005)/NORMAL]
C104  100nF  [C/SM/0805/IPC-7351 (2005)/NORMAL]
C105  27pF  [C/SM/0805/IPC-7351 (2005)/NORMAL]
LED14  LH R974  [LED/SM/0805/IPC-7351 (2005)/NORMAL]
R133  2k7  [R/SM/0805/IPC-7351 (2005)/NORMAL]
R134  16k  [R/SM/0805/IPC-7351 (2005)/NORMAL]
R135  20R0/0.25W/0.1%  [R/SM/1206/IPC-7351 (2005)/NORMAL]
R136  100k/0.1%  [R/SM/0805/IPC-7351 (2005)/NORMAL]
R137  10k  [R/SM/0805/IPC-7351 (2005)/NORMAL]
R138  20R0/0.25W/0.1%  [R/SM/1206/IPC-7351 (2005)/NORMAL]
R139  10R/0.66W/5%  [R/SM/1206/IPC-7351 (2005)/NORMAL]
R140  20R0/0.25W/0.1%  [R/SM/1206/IPC-7351 (2005)/NORMAL]
R141  100k/0.1%  [R/SM/0805/IPC-7351 (2005)/NORMAL]
R142  20R0/0.25W/0.1%  [R/SM/1206/IPC-7351 (2005)/NORMAL]
R143  100k/0.1%  [R/SM/0805/IPC-7351 (2005)/NORMAL]
R144  100k/0.1%  [R/SM/0805/IPC-7351 (2005)/NORMAL]
R145  1k20/0.1%  [R/SM/0805/IPC-7351 (2005)/NORMAL]
R146  2k00/0.1%  [R/SM/0805/IPC-7351 (2005)/NORMAL]
TVS52  SMAJ8.5CA  [SM/DO214AC/IPC-7351 (2005)/NORMAL]
U34  OPA132  [SM/SOIC.050/08/WB.150/L.200/IPC-7351 (2005)/NORMAL]
U35  LMH6321  [SM/TO263/D2PAK/THV 42X.012/7/IPC-7351 (2005)/NORMAL]
U36  AD8130  [SM/SOIC.050/08/WB.150/L.200/IPC-7351 (2005)/NORMAL]
sheet B4B06
C118  100nF  [C/SM/0805/IPC-7351 (2005)/NORMAL]
C119  10uF/25V  [C/SM/1210/IPC-7351 (2005)/NORMAL]
C120  10uF/25V  [C/SM/1210/IPC-7351 (2005)/NORMAL]
C121  1nF  [C/SM/0805/IPC-7351 (2005)/NORMAL]
C122  1nF  [C/SM/0805/IPC-7351 (2005)/NORMAL]
C123  27pF  [C/SM/0805/IPC-7351 (2005)/NORMAL]
C124  1nF  [C/SM/0805/IPC-7351 (2005)/NORMAL]
C125  100nF  [C/SM/0805/IPC-7351 (2005)/NORMAL]
C126  100nF  [C/SM/0805/IPC-7351 (2005)/NORMAL]
C127  100nF  [C/SM/0805/IPC-7351 (2005)/NORMAL]
C128  100nF  [C/SM/0805/IPC-7351 (2005)/NORMAL]
C129  27pF  [C/SM/0805/IPC-7351 (2005)/NORMAL]
LED16  LH R974  [LED/SM/0805/IPC-7351 (2005)/NORMAL]
R161  2k7  [R/SM/0805/IPC-7351 (2005)/NORMAL]
R162  20R0/0.25W/0.1%  [R/SM/1206/IPC-7351 (2005)/NORMAL]
R163  16k  [R/SM/0805/IPC-7351 (2005)/NORMAL]
R164  100k/0.1%  [R/SM/0805/IPC-7351 (2005)/NORMAL]
R165  10k  [R/SM/0805/IPC-7351 (2005)/NORMAL]
R166  20R0/0.25W/0.1%  [R/SM/1206/IPC-7351 (2005)/NORMAL]
R167  10R/0.66W/5%  [R/SM/1206/IPC-7351 (2005)/NORMAL]
R168  20R0/0.25W/0.1%  [R/SM/1206/IPC-7351 (2005)/NORMAL]
R169  100k/0.1%  [R/SM/0805/IPC-7351 (2005)/NORMAL]
R170  20R0/0.25W/0.1%  [R/SM/1206/IPC-7351 (2005)/NORMAL]
R171  100k/0.1%  [R/SM/0805/IPC-7351 (2005)/NORMAL]
R172  100k/0.1%  [R/SM/0805/IPC-7351 (2005)/NORMAL]
R173  1k20/0.1%  [R/SM/0805/IPC-7351 (2005)/NORMAL]
R174  2k00/0.1%  [R/SM/0805/IPC-7351 (2005)/NORMAL]
TVS54  SMAJ8.5CA  [SM/DO214AC/IPC-7351 (2005)/NORMAL]
U40  OPA132  [SM/SOIC.050/08/WB.150/L.200/IPC-7351 (2005)/NORMAL]
U41  LMH6321  [SM/TO263/D2PAK/THV 42X.012/7/IPC-7351 (2005)/NORMAL]
U42  AD8130  [SM/SOIC.050/08/WB.150/L.200/IPC-7351 (2005)/NORMAL]
sheet B4B07
C130  100nF  [C/SM/0805/IPC-7351 (2005)/NORMAL]
C131  10uF/25V  [C/SM/1210/IPC-7351 (2005)/NORMAL]
C132  10uF/25V  [C/SM/1210/IPC-7351 (2005)/NORMAL]
C133  1nF  [C/SM/0805/IPC-7351 (2005)/NORMAL]
C134  1nF  [C/SM/0805/IPC-7351 (2005)/NORMAL]
C135  820pF  [C/SM/0805/IPC-7351 (2005)/NORMAL]
C136  1nF  [C/SM/0805/IPC-7351 (2005)/NORMAL]
C137  100nF  [C/SM/0805/IPC-7351 (2005)/NORMAL]
C138  100nF  [C/SM/0805/IPC-7351 (2005)/NORMAL]
C139  100nF  [C/SM/0805/IPC-7351 (2005)/NORMAL]
C140  100nF  [C/SM/0805/IPC-7351 (2005)/NORMAL]
C141  27pF  [C/SM/0805/IPC-7351 (2005)/NORMAL]
LED17  LH R974  [LED/SM/0805/IPC-7351 (2005)/NORMAL]
R175  2k7  [R/SM/0805/IPC-7351 (2005)/NORMAL]
R176  75k  [R/SM/0805/IPC-7351 (2005)/NORMAL]
R177  100R/0.1%  [R/SM/1206/IPC-7351 (2005)/NORMAL]
R178  100k/0.1%  [R/SM/0805/IPC-7351 (2005)/NORMAL]
R179  100R/0.1%  [R/SM/1206/IPC-7351 (2005)/NORMAL]
R180  10k  [R/SM/0805/IPC-7351 (2005)/NORMAL]
R181  47R/0.25W/5%  [R/SM/1206/IPC-7351 (2005)/NORMAL]
R182  100R/0.1%  [R/SM/1206/IPC-7351 (2005)/NORMAL]
R183  100k/0.1%  [R/SM/0805/IPC-7351 (2005)/NORMAL]
R184  100R/0.1%  [R/SM/1206/IPC-7351 (2005)/NORMAL]
R185  100k/0.1%  [R/SM/0805/IPC-7351 (2005)/NORMAL]
R186  100k/0.1%  [R/SM/0805/IPC-7351 (2005)/NORMAL]
R187  1k20/0.1%  [R/SM/0805/IPC-7351 (2005)/NORMAL]
R188  2k00/0.1%  [R/SM/0805/IPC-7351 (2005)/NORMAL]
TVS55  SMAJ8.5CA  [SM/DO214AC/IPC-7351 (2005)/NORMAL]
U43  OPA132  [SM/SOIC.050/08/WB.150/L.200/IPC-7351 (2005)/NORMAL]
U44  LMH6321  [SM/TO263/D2PAK/THV 42X.012/7/IPC-7351 (2005)/NORMAL]
U45  AD8130  [SM/SOIC.050/08/WB.150/L.200/IPC-7351 (2005)/NORMAL]
sheet B4B10
C166  100nF  [C/SM/0805/IPC-7351 (2005)/NORMAL]
C167  10uF/25V  [C/SM/1210/IPC-7351 (2005)/NORMAL]
C168  10uF/25V  [C/SM/1210/IPC-7351 (2005)/NORMAL]
C169  1nF  [C/SM/0805/IPC-7351 (2005)/NORMAL]
C170  1nF  [C/SM/0805/IPC-7351 (2005)/NORMAL]
C171  27pF  [C/SM/0805/IPC-7351 (2005)/NORMAL]
C172  1nF  [C/SM/0805/IPC-7351 (2005)/NORMAL]
C173  100nF  [C/SM/0805/IPC-7351 (2005)/NORMAL]
C174  100nF  [C/SM/0805/IPC-7351 (2005)/NORMAL]
C175  100nF  [C/SM/0805/IPC-7351 (2005)/NORMAL]
C176  100nF  [C/SM/0805/IPC-7351 (2005)/NORMAL]
C177  27pF  [C/SM/0805/IPC-7351 (2005)/NORMAL]
LED20  LH R974  [LED/SM/0805/IPC-7351 (2005)/NORMAL]
R217  2k7  [R/SM/0805/IPC-7351 (2005)/NORMAL]
R218  16k  [R/SM/0805/IPC-7351 (2005)/NORMAL]
R219  20R0/0.25W/0.1%  [R/SM/1206/IPC-7351 (2005)/NORMAL]
R220  100k/0.1%  [R/SM/0805/IPC-7351 (2005)/NORMAL]
R221  10k  [R/SM/0805/IPC-7351 (2005)/NORMAL]
R222  20R0/0.25W/0.1%  [R/SM/1206/IPC-7351 (2005)/NORMAL]
R223  10R/0.66W/5%  [R/SM/1206/IPC-7351 (2005)/NORMAL]
R224  20R0/0.25W/0.1%  [R/SM/1206/IPC-7351 (2005)/NORMAL]
R225  100k/0.1%  [R/SM/0805/IPC-7351 (2005)/NORMAL]
R226  20R0/0.25W/0.1%  [R/SM/1206/IPC-7351 (2005)/NORMAL]
R227  100k/0.1%  [R/SM/0805/IPC-7351 (2005)/NORMAL]
R228  100k/0.1%  [R/SM/0805/IPC-7351 (2005)/NORMAL]
R229  1k20/0.1%  [R/SM/0805/IPC-7351 (2005)/NORMAL]
R230  2k00/0.1%  [R/SM/0805/IPC-7351 (2005)/NORMAL]
TVS58  SMAJ8.5CA  [SM/DO214AC/IPC-7351 (2005)/NORMAL]
U52  OPA132  [SM/SOIC.050/08/WB.150/L.200/IPC-7351 (2005)/NORMAL]
U53  LMH6321  [SM/TO263/D2PAK/THV 42X.012/7/IPC-7351 (2005)/NORMAL]
U54  AD8130  [SM/SOIC.050/08/WB.150/L.200/IPC-7351 (2005)/NORMAL]
sheet B4B17
C250  100nF  [C/SM/0805/IPC-7351 (2005)/NORMAL]
C251  100nF  [C/SM/0805/IPC-7351 (2005)/NORMAL]
C252  1uF  [C/SM/1206/IPC-7351 (2005)/NORMAL]
JP1  HEADER 5X2  [DIP.100/10/W.600/L.500/.064/.028]
R315  9k1  [R/SM/0805/IPC-7351 (2005)/NORMAL]
R316  0R  [R/SM/0805/IPC-7351 (2005)/NORMAL]
TVS66  SMAJ10A  [SM/DO214AC/IPC-7351 (2005)/NORMAL]
U73  AD5293-20  [SM/TSSOP/.0255/14/WB.180/L.200/IPC-7351 (2005)/NORMAL]
sheet B4B18
C253  100nF  [C/SM/0805/IPC-7351 (2005)/NORMAL]
C254  100nF  [C/SM/0805/IPC-7351 (2005)/NORMAL]
C255  1uF  [C/SM/1206/IPC-7351 (2005)/NORMAL]
JP2  HEADER 5X2  [DIP.100/10/W.600/L.500/.064/.028]
R317  6k80  [R/SM/0805/IPC-7351 (2005)/NORMAL]
R318  0R  [R/SM/0805/IPC-7351 (2005)/NORMAL]
TVS67  SMAJ10A  [SM/DO214AC/IPC-7351 (2005)/NORMAL]
U74  AD5293-20  [SM/TSSOP/.0255/14/WB.180/L.200/IPC-7351 (2005)/NORMAL]
sheet B4B19
C256  100nF  [C/SM/0805/IPC-7351 (2005)/NORMAL]
C257  100nF  [C/SM/0805/IPC-7351 (2005)/NORMAL]
C258  1uF  [C/SM/1206/IPC-7351 (2005)/NORMAL]
JP3  HEADER 5X2  [DIP.100/10/W.600/L.500/.064/.028]
R319  9k1  [R/SM/0805/IPC-7351 (2005)/NORMAL]
R320  0R  [R/SM/0805/IPC-7351 (2005)/NORMAL]
TVS68  SMAJ10A  [SM/DO214AC/IPC-7351 (2005)/NORMAL]
U75  AD5293-20  [SM/TSSOP/.0255/14/WB.180/L.200/IPC-7351 (2005)/NORMAL]
sheet B4B20
C259  100nF  [C/SM/0805/IPC-7351 (2005)/NORMAL]
C260  100nF  [C/SM/0805/IPC-7351 (2005)/NORMAL]
C261  1uF  [C/SM/1206/IPC-7351 (2005)/NORMAL]
JP4  HEADER 5X2  [DIP.100/10/W.600/L.500/.064/.028]
R321  1k65  [R/SM/0805/IPC-7351 (2005)/NORMAL]
R322  0R  [R/SM/0805/IPC-7351 (2005)/NORMAL]
TVS69  SMAJ10A  [SM/DO214AC/IPC-7351 (2005)/NORMAL]
U76  AD5293-20  [SM/TSSOP/.0255/14/WB.180/L.200/IPC-7351 (2005)/NORMAL]
sheet B7B05
C106  100nF  [C/SM/0805/IPC-7351 (2005)/NORMAL]
C107  10uF/25V  [C/SM/1210/IPC-7351 (2005)/NORMAL]
C108  10uF/25V  [C/SM/1210/IPC-7351 (2005)/NORMAL]
C109  1nF  [C/SM/0805/IPC-7351 (2005)/NORMAL]
C110  1nF  [C/SM/0805/IPC-7351 (2005)/NORMAL]
C111  27pF  [C/SM/0805/IPC-7351 (2005)/NORMAL]
C112  1nF  [C/SM/0805/IPC-7351 (2005)/NORMAL]
C113  100nF  [C/SM/0805/IPC-7351 (2005)/NORMAL]
C114  100nF  [C/SM/0805/IPC-7351 (2005)/NORMAL]
C115  100nF  [C/SM/0805/IPC-7351 (2005)/NORMAL]
C116  100nF  [C/SM/0805/IPC-7351 (2005)/NORMAL]
C117  27pF  [C/SM/0805/IPC-7351 (2005)/NORMAL]
LED15  LH R974  [LED/SM/0805/IPC-7351 (2005)/NORMAL]
R147  2k7  [R/SM/0805/IPC-7351 (2005)/NORMAL]
R148  16k  [R/SM/0805/IPC-7351 (2005)/NORMAL]
R149  20R0/0.25W/0.1%  [R/SM/1206/IPC-7351 (2005)/NORMAL]
R150  100k/0.1%  [R/SM/0805/IPC-7351 (2005)/NORMAL]
R151  10k  [R/SM/0805/IPC-7351 (2005)/NORMAL]
R152  20R0/0.25W/0.1%  [R/SM/1206/IPC-7351 (2005)/NORMAL]
R153  10R/0.66W/5%  [R/SM/1206/IPC-7351 (2005)/NORMAL]
R154  20R0/0.25W/0.1%  [R/SM/1206/IPC-7351 (2005)/NORMAL]
R155  100k/0.1%  [R/SM/0805/IPC-7351 (2005)/NORMAL]
R156  20R0/0.25W/0.1%  [R/SM/1206/IPC-7351 (2005)/NORMAL]
R157  100k/0.1%  [R/SM/0805/IPC-7351 (2005)/NORMAL]
R158  100k/0.1%  [R/SM/0805/IPC-7351 (2005)/NORMAL]
R159  1k20/0.1%  [R/SM/0805/IPC-7351 (2005)/NORMAL]
R160  2k00/0.1%  [R/SM/0805/IPC-7351 (2005)/NORMAL]
TVS53  SMAJ8.5CA  [SM/DO214AC/IPC-7351 (2005)/NORMAL]
U37  OPA132  [SM/SOIC.050/08/WB.150/L.200/IPC-7351 (2005)/NORMAL]
U38  LMH6321  [SM/TO263/D2PAK/THV 42X.012/7/IPC-7351 (2005)/NORMAL]
U39  AD8130  [SM/SOIC.050/08/WB.150/L.200/IPC-7351 (2005)/NORMAL]

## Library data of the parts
C70 C77-C80 C82 C89-C92 C94 C101-C104 C106 C113-C116 C118 C125-C128 C130 C137-C140 C166 C173-C176 C250 C251 C253 C254 C256 C257 C259 C260 = CAP_NP: RS: 723-5058
C71 C72 C83 C84 C95 C96 C107 C108 C119 C120 C131 C132 C167 C168 = CAP_NP: RS: 790-0632
C73 C74 C76 C85 C86 C88 C97 C98 C100 C109 C110 C112 C121 C122 C124 C133 C134 C136 C169 C170 C172 = CAP_NP: RS: 723-6196
C75 C81 C87 C93 C99 C105 C111 C117 C123 C129 C141 C171 C177 = CAP_NP: Farnell: 1414683
LED12-LED17 LED20 = LED: RS: 654-5818
R105 R106 R109 R119 R120 R123 R133 R134 R137 R147 R148 R151 R161 R163 R165 R175 R176 R180 R217 R218 R221 R315-R322 = R
R107 R110 R112 R114 R121 R124 R126 R128 R135 R138 R140 R142 R149 R152 R154 R156 R162 R166 R168 R170 R219 R222 R224 R226 = R: Farnell: 1501421
R108 R113 R115 R116 R122 R127 R129 R130 R136 R141 R143 R144 R150 R155 R157 R158 R164 R169 R171 R172 R178 R183 R185 R186 R220 R225 R227 R228 = R: RS: 566-765
R111 R125 R139 R153 R167 R223 = R: RS: 153-696
R117 R131 R145 R159 R173 R187 R229 = R: RS: 565-926
R118 R132 R146 R160 R174 R188 R230 = R: RS: 828-0554
TVS50-TVS55 TVS58 = TVS-BIDIRECTIONAL
U28 U31 U34 U37 U40 U43 U52 = OPA132_(SOIC8): MFR. P/N: OPA132UA; RS: 218-8275
U29 U32 U35 U38 U41 U44 U53 = LMH6321_(TO263)_0: MFR. P/N: LMH6321TS/NOPB; RS: 655-3831
U30 U33 U36 U39 U42 U45 U54 = AD8130_(SOIC8): MFR. P/N: AD8130ARZ; RS: 497-2268
C135 = CAP_NP: Farnell: 2409058
R177 R179 R182 R184 = R: RS: 669-6503
R181 = R: RS: 721-8823
C252 C255 C258 C261 = CAP_NP: RS: 723-6584
JP1-JP4 = HEADER_5X2_0: RS: 702-2760
TVS66-TVS69 = DIODE_ZENER_1: RS: 822-8528
U73-U76 = AD5293: MFR. P/N: AD5293BRUZ-20; RS: 758-9601

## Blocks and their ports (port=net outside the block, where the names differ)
IF MicroZed = schematic B2 IF MicroZed, on sheet B0: DAC_D[0..16], DAC_SYNC=N09915, DO_SCL=N01772, DO_SDA=N01784, DO_RST=N01802, DI_RST=N01830, DI_SDA=N01826, DI_SCL=N01806, VCCIO_EN=N08147, PG_CARRIER=N08032, AD_/CS=N05412, AD_SCL=N23945, AD_SDA=N23949, DRIVER_GPO_DOWN_00=N09557, DRIVER_GPO_DOWN_01=N09579, DRIVER_GPO_DOWN_02=N09603, DRIVER_GPO_DOWN_03=N09627, DRIVER_GPO_DOWN_04=N09651, DRIVER_GPO_DOWN_05=N09675, DRIVER_GPO_DOWN_06=N09699, DRIVER_GPO_UP_00=N09545, DRIVER_GPO_UP_01=N09575, DRIVER_GPO_UP_02=N09599, DRIVER_GPO_UP_03=N09623, DRIVER_GPO_UP_04=N09647, DRIVER_GPO_UP_05=N09671, DRIVER_GPO_UP_06=N09695, NTC_SYNC=N14846, NTC_SCLK=N14834, NTC_D[0..3], DAC_SCLK[0..5], DI_/INT=N24584
Drivers IGBT = schematic B5 Drivers IGBT, on sheet B0: DRIVER_GPO_UP_00=N09545, DRIVER_GPO_UP_01=N09575, DRIVER_GPO_UP_02=N09599, DRIVER_GPO_UP_03=N09623, DRIVER_GPO_UP_04=N09647, DRIVER_GPO_UP_05=N09671, DRIVER_GPO_UP_06=N09695, DRIVER_GPO_DOWN_00=N09557, DRIVER_GPO_DOWN_01=N09579, DRIVER_GPO_DOWN_02=N09603, DRIVER_GPO_DOWN_03=N09627, DRIVER_GPO_DOWN_04=N09651, DRIVER_GPO_DOWN_05=N09675, DRIVER_GPO_DOWN_06=N09699
ECPs = schematic Engineering Change Proposals, on sheet B0: no ports
E/S Digitales = schematic , on sheet B0: DI_SCL=N01806, DI_SDA=N01826, DI_RST=N01830, DO_RST=N01802, DO_SCL=N01772, DO_SDA=N01784, AD_SCL=N23945, AD_SDA=N23949, AD_/CS=N05412, DIG_OUT_17_OC=N23731, DI_/INT=N24584
Alimentacion = schematic B1 Alimentacion, on sheet B0: PG_CARRIER=N08032, VCCIO_EN=N08147
E/S Analogicas = schematic , on sheet B0: DAC_SYNC=N09915, DIG_OUT_17_OC=N23731, NTC_SCLK=N14834, NTC_D[0..3], NTC_SYNC=N14846, DAC_SCLK[0..5], DAC_D[0..16]

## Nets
+5VA: U73.1(/RST) U73.8(VLOGIC) U74.1(/RST) U74.8(VLOGIC) U75.1(/RST) U75.8(VLOGIC) U76.1(/RST) U76.8(VLOGIC) ; also on sheet 18 24
+12VA: R106.2 R120.2 R134.2 R148.2 R163.2 R176.2 R218.2 U30.3(/PD) U30.7(+Vs) U33.3(/PD) U33.7(+Vs) U36.3(/PD) U36.7(+Vs) U39.3(/PD) U39.7(+Vs) U42.3(/PD) U42.7(+Vs) U45.3(/PD) U45.7(+Vs) U54.3(/PD) U54.7(+Vs) ; also on sheet 13 14 15 16 17 19 20 21 22 24
+15VA: C70.2 C71.1 C82.2 C83.1 C94.2 C95.1 C106.2 C107.1 C118.2 C119.1 C130.2 C131.1 C166.2 C167.1 LED12.2(ANODE) LED13.2(ANODE) LED14.2(ANODE) LED15.2(ANODE) LED16.2(ANODE) LED17.2(ANODE) LED20.2(ANODE) U28.7(+Vs) U29.5(+Vs) U31.7(+Vs) U32.5(+Vs) U34.7(+Vs) U35.5(+Vs) U37.7(+Vs) U38.5(+Vs) U40.7(+Vs) U41.5(+Vs) U43.7(+Vs) U44.5(+Vs) U52.7(+Vs) U53.5(+Vs) ; also on sheet 13 14 15 16 17 19 20 21 22 24
+22VA: U73.6(VDD) U74.6(VDD) U75.6(VDD) U76.6(VDD) ; also on sheet 24
-12VA: U30.2(-Vs) U33.2(-Vs) U36.2(-Vs) U39.2(-Vs) U42.2(-Vs) U45.2(-Vs) U54.2(-Vs) ; also on sheet 13 14 15 16 17 19 20 21 22 24
-15VA: C70.1 C72.1 C82.1 C84.1 C94.1 C96.1 C106.1 C108.1 C118.1 C120.1 C130.1 C132.1 C166.1 C168.1 U28.4(-Vs) U29.4(-Vs) U31.4(-Vs) U32.4(-Vs) U34.4(-Vs) U35.4(-Vs) U37.4(-Vs) U38.4(-Vs) U40.4(-Vs) U41.4(-Vs) U43.4(-Vs) U44.4(-Vs) U52.4(-Vs) U53.4(-Vs) ; also on sheet 13 14 15 16 17 19 20 21 22 24
GND_ANALOG: C71.2 C72.2 C73.1 C74.1 C75.2 C77.1 C78.1 C79.1 C80.1 C81.1 C83.2 C84.2 C85.1 C86.1 C87.2 C89.1 C90.1 C91.1 C92.1 C93.1 C95.2 C96.2 C97.1 C98.1 C99.2 C101.1 C102.1 C103.1 C104.1 C105.1 C107.2 C108.2 C109.1 C110.1 C111.2 C113.1 C114.1 C115.1 C116.1 C117.1 C119.2 C120.2 C121.1 C122.1 C123.2 C125.1 C126.1 C127.1 C128.1 C129.1 C131.2 C132.2 C133.1 C134.1 C135.2 C137.1 C138.1 C139.1 C140.1 C141.1 C167.2 C168.2 C169.1 C170.1 C171.2 C173.1 C174.1 C175.1 C176.1 C177.1 C250.1 C251.1 C252.2 C253.1 C254.1 C255.2 C256.1 C257.1 C258.2 C259.1 C260.1 C261.2 R113.1 R118.2 R127.1 R132.2 R141.1 R146.2 R155.1 R160.2 R169.1 R174.2 R183.1 R188.2 R225.1 R230.2 TVS50.2 TVS51.2 TVS52.2 TVS53.2 TVS54.2 TVS55.2 TVS58.2 U29.2(GND) U30.4(REF) U32.2(GND) U33.4(REF) U35.2(GND) U36.4(REF) U38.2(GND) U39.4(REF) U41.2(GND) U42.4(REF) U44.2(GND) U45.4(REF) U53.2(GND) U54.4(REF) U73.2(VSS) U73.9(GND) U74.2(VSS) U74.9(GND) U75.2(VSS) U75.9(GND) U76.2(VSS) U76.9(GND) ; also on sheet 13 14 15 16 17 18 19 20 21 22 24 25 26 31 32 33 34 35 36 37 38
VCC_CIRCLE: C73.2 C74.2 C77.2 C78.2 C79.2 C80.2 C85.2 C86.2 C89.2 C90.2 C91.2 C92.2 C97.2 C98.2 C101.2 C102.2 C103.2 C104.2 C109.2 C110.2 C113.2 C114.2 C115.2 C116.2 C121.2 C122.2 C125.2 C126.2 C127.2 C128.2 C133.2 C134.2 C137.2 C138.2 C139.2 C140.2 C169.2 C170.2 C173.2 C174.2 C175.2 C176.2 C250.2 C251.2 C253.2 C254.2 C256.2 C257.2 C259.2 C260.2 ; also on sheet 13 14 15 16 17 18 19 20 21 22 27 28 29 30
Vin: R108.1 R122.1 R136.1 R150.1 R164.1 R178.1 R220.1 ; also on sheet 13 14 15 16 17 19 20 21 22
DIN: U73.10(DIN) U74.10(DIN) U75.10(DIN) U76.10(DIN)
M: R111.2 R125.2 R139.2 R153.2 R167.2 R181.2 R223.2 TVS50.1 TVS51.1 TVS52.1 TVS53.1 TVS54.1 TVS55.1 TVS58.1 ; also on sheet 13 14 15 16 17 19 20 21 22
NTC+: R315.1 R317.1 R319.1 R321.1 TVS66.1(CATHODE) TVS67.1(CATHODE) TVS68.1(CATHODE) TVS69.1(CATHODE) U73.3(A) U73.4(W) U74.3(A) U74.4(W) U75.3(A) U75.4(W) U76.3(A) U76.4(W)
NTC-: JP1.(7) JP2.(7) JP3.(9) JP4.(7) R316.1 R318.1 R320.1 R322.1 TVS66.2(ANODE) TVS67.2(ANODE) TVS68.2(ANODE) TVS69.2(ANODE)
SCLK: U73.11(SCLK) U74.11(SCLK) U75.11(SCLK) U76.11(SCLK)
VREF/2: R115.2 R129.2 R143.2 R158.2 R171.2 R185.2 R227.2 ; also on sheet 13 14 15 16 17 18 19 20 21 22

Not connected (* = marked no-connect by the designer): C75 1; C76 1 2; C81 2; C87 1; C88 1 2; C93 2; C99 1; C100 1 2; C105 2; C111 1; C112 1 2; C117 2; C123 1; C124 1 2; C129 2; C135 1; C136 1 2; C141 2; C171 1; C172 1 2; C177 2; C252 1; C255 1; C258 1; C261 1; LED12 1(CATHODE); LED13 1(CATHODE); LED14 1(CATHODE); LED15 1(CATHODE); LED16 1(CATHODE); LED17 1(CATHODE); LED20 1(CATHODE); R105 1 2; R106 1; R107 1 2; R108 2; R109 1 2; R110 1 2; R111 1; R112 1 2; R113 2; R114 1 2; R115 1; R116 1 2; R117 1 2; R118 1; R119 1 2; R120 1; R121 1 2; R122 2; R123 1 2; R124 1 2; R125 1; R126 1 2; R127 2; R128 1 2; R129 1; R130 1 2; R131 1 2; R132 1; R133 1 2; R134 1; R135 1 2; R136 2; R137 1 2; R138 1 2; R139 1; R140 1 2; R141 2; R142 1 2; R143 1; R144 1 2; R145 1 2; R146 1; R147 1 2; R148 1; R149 1 2; R150 2; R151 1 2; R152 1 2; R153 1; R154 1 2; R155 2; R156 1 2; R157 1 2; R158 1; R159 1 2; R160 1; R161 1 2; R162 1 2; R163 1; R164 2; R165 1 2; R166 1 2; R167 1; R168 1 2; R169 2; R170 1 2; R171 1; R172 1 2; R173 1 2; R174 1; R175 1 2; R176 1; R177 1 2; R178 2; R179 1 2; R180 1 2; R181 1; R182 1 2; R183 2; R184 1 2; R185 1; R186 1 2; R187 1 2; R188 1; R217 1 2; R218 1; R219 1 2; R220 2; R221 1 2; R222 1 2; R223 1; R224 1 2; R225 2; R226 1 2; R227 1; R228 1 2; R229 1 2; R230 1; R315 2; R316 2; R317 2; R318 2; R319 2; R320 2; R321 2; R322 2; U28 1(O1) 2(-) 3(+) 6(Out) 8(O2); U29 1(Vin) 3(Out) 6(/EF) 7(CL) 8(-15VA); U30 1(+) 5(FB) 6(Out) 8(-); U31 1(O1) 2(-) 3(+) 6(Out) 8(O2); U32 1(Vin) 3(Out) 6(/EF) 7(CL) 8(-15VA); U33 1(+) 5(FB) 6(Out) 8(-); U34 1(O1) 2(-) 3(+) 6(Out) 8(O2); U35 1(Vin) 3(Out) 6(/EF) 7(CL) 8(-15VA); U36 1(+) 5(FB) 6(Out) 8(-); U37 1(O1) 2(-) 3(+) 6(Out) 8(O2); U38 1(Vin) 3(Out) 6(/EF) 7(CL) 8(-15VA); U39 1(+) 5(FB) 6(Out) 8(-); U40 1(O1) 2(-) 3(+) 6(Out) 8(O2); U41 1(Vin) 3(Out) 6(/EF) 7(CL) 8(-15VA); U42 1(+) 5(FB) 6(Out) 8(-); U43 1(O1) 2(-) 3(+) 6(Out) 8(O2); U44 1(Vin) 3(Out) 6(/EF) 7(CL) 8(-15VA); U45 1(+) 5(FB) 6(Out) 8(-); U52 1(O1) 2(-) 3(+) 6(Out) 8(O2); U53 1(Vin) 3(Out) 6(/EF) 7(CL) 8(-15VA); U54 1(+) 5(FB) 6(Out) 8(-); U73 5(B) 7(EC) 12(/SYNC) 13(SDO) 14(RDY); U74 5(B) 7(EC) 12(/SYNC) 13(SDO) 14(RDY); U75 5(B) 7(EC) 12(/SYNC) 13(SDO) 14(RDY); U76 5(B) 7(EC) 12(/SYNC) 13(SDO) 14(RDY)

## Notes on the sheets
sheet 2
- For RNTC=5k0 Program RWB=18k9 (3C7h)
  For RNTC=3k3 Program RWB=6k41 (148h)
  For RNTC=1k0 Program RWB=1k17 (03Ch)
sheet 3
- Vin: 0,5 a 4,5V
  M: -250 a +250mA
sheet 4
- For RNTC=6.0k Program RWB=17k6 (385h)
  For RNTC=2.0k Program RWB=2k56 (083h)
  For RNTC=0.4k Program RWB=418R (015h)
  For RNTC=0.3k Program RWB=310R (00Fh)
sheet 5
- For RNTC=6.0k Program RWB=17k6 (385h)
  For RNTC=0.5k Program RWB=529R (01Bh)
  For RNTC=0.3k Program RWB=310R (00Fh)
sheet 6
- Vin: 0,5 a 4,5V
  M: -250 a +250mA
sheet 7
- For RPt1000=1k5 Program RWB=16k5 (34Ch)
  For RPt1000=1k3 Program RWB=6k13 (139h)
  For RPt1000=1k0 Program RWB=2k54 (081h)
  For RPt1000=0k9 Program RWB=1k89 (065h)
sheet 8
- Vin: 0,5 a 4,5V
  M: -250 a +250mA
sheet 9
- Vin: 0,5 a 4,5V
  M: -250 a +250mA
sheet 10
- Vin: 0,5 a 4,5V
  M: -250 a +250mA
sheet 11
- Vin: 0,5 a 4,5V
  M: -50 a +50mA
- (Es bidireccional aunque
  no hace falta)
sheet 12
- Vin: 0,5 a 4,5V
  M: -250 a +250mA
